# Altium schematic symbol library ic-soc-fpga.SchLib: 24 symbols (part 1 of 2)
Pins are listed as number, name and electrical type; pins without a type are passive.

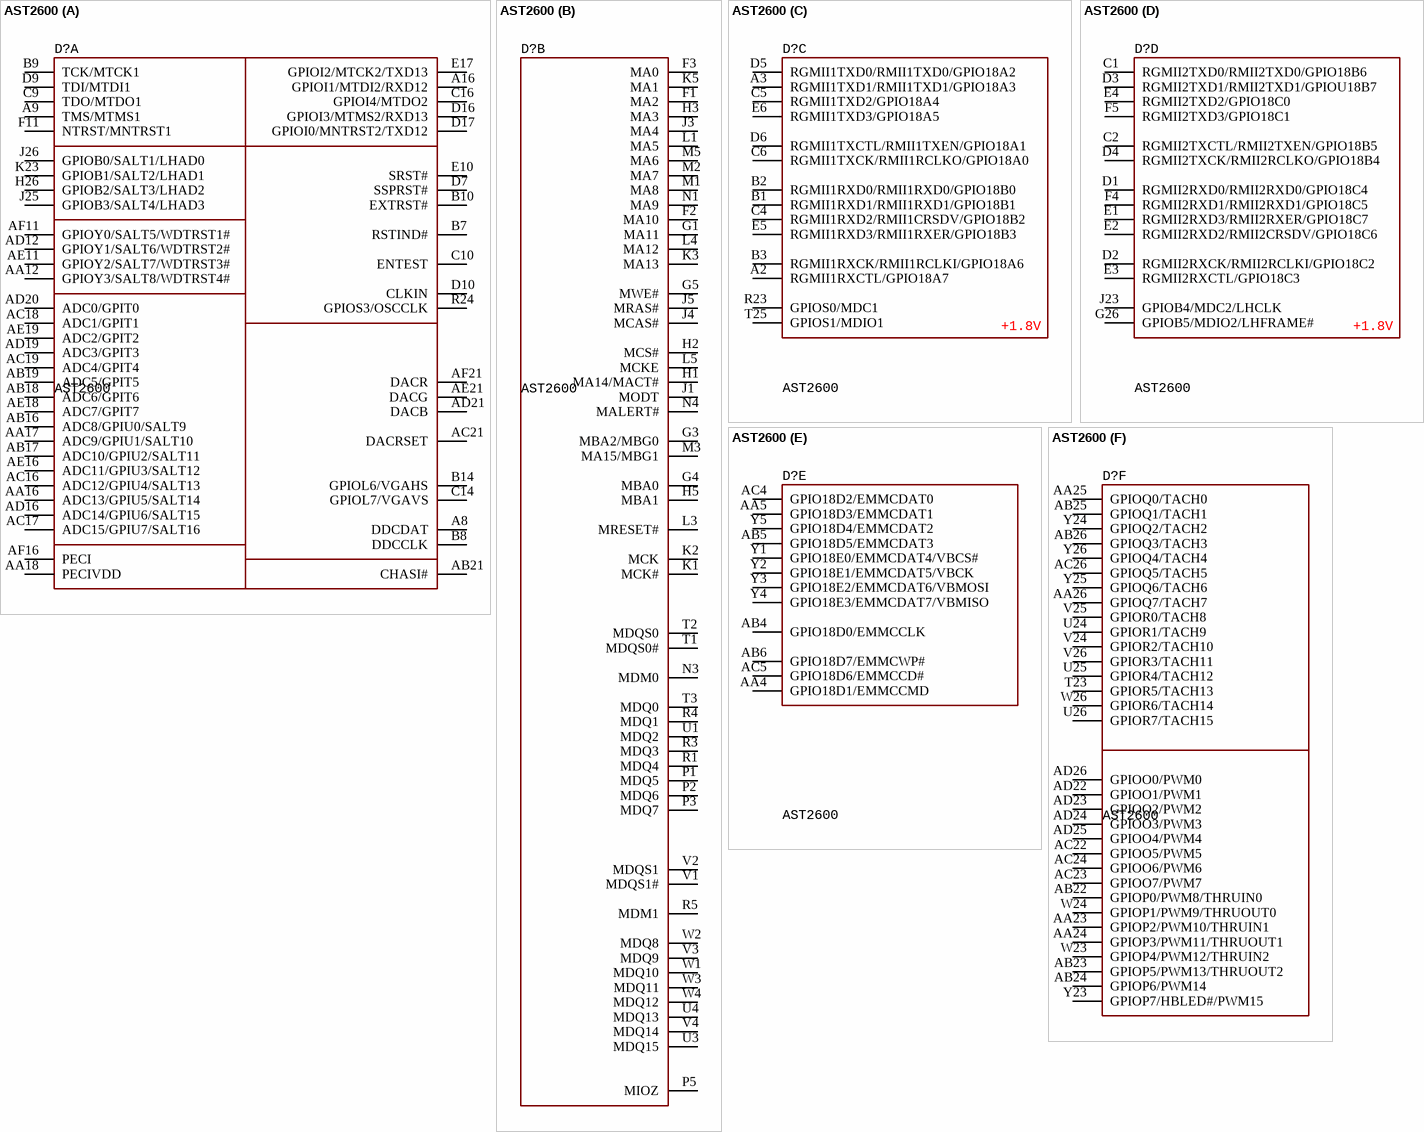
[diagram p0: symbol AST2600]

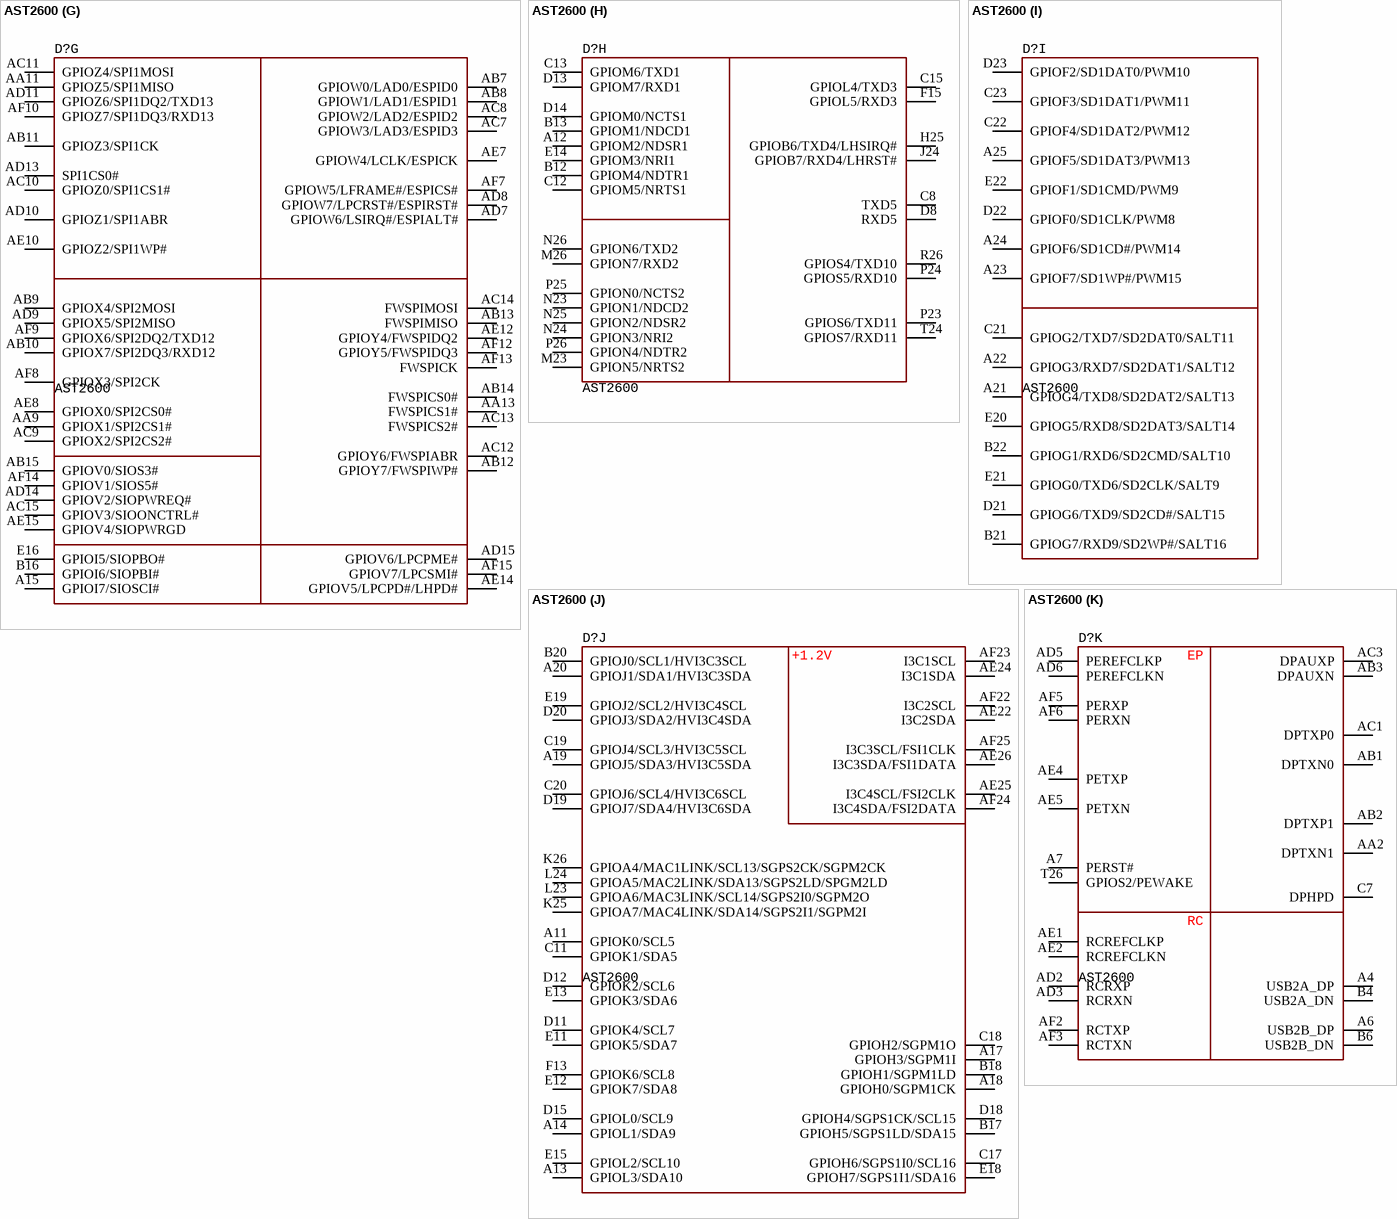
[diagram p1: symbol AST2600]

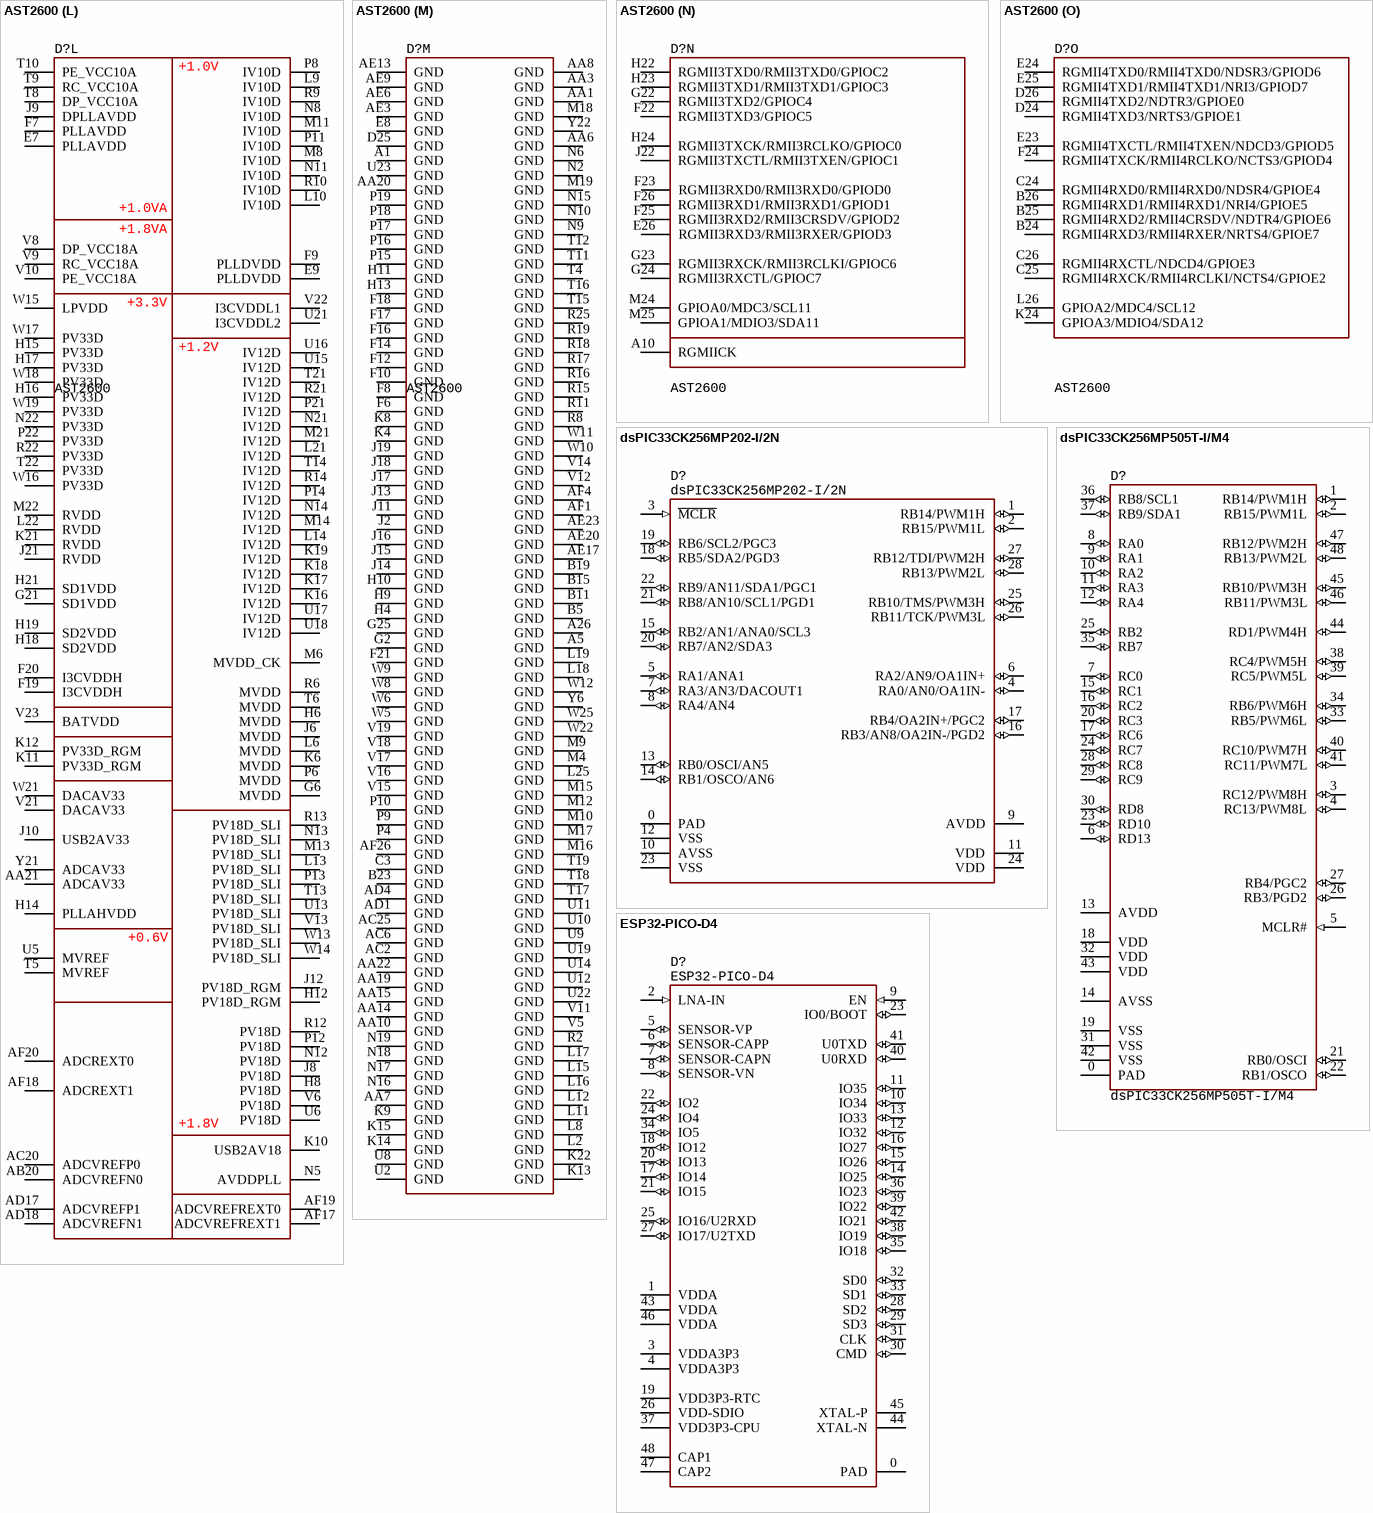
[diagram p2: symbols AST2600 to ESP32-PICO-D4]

## AST2600
designator D?
ARM SoC, Cortex-A7/M3, 1.2GHz, TFBGA-624, 0...+95°C; Manufacturer: ASPEED
footprint 624-TFBGA (21x21, pitch 0.8)
part A pins: A8 DDCDAT, A9 TMS/MTMS1, A16 GPIOI1/MTDI2/RXD12, AA12 GPIOY3/SALT8/WDTRST4#, AA16 ADC13/GPIU5/SALT14, AA17 ADC9/GPIU1/SALT10, AA18 PECIVDD, AB16 ADC8/GPIU0/SALT9, AB17 ADC10/GPIU2/SALT11, AB18 ADC6/GPIT6, AB19 ADC5/GPIT5, AB21 CHASI#, AC16 ADC12/GPIU4/SALT13, AC17 ADC15/GPIU7/SALT16, AC18 ADC1/GPIT1, AC19 ADC4/GPIT4, AC21 DACRSET, AD12 GPIOY1/SALT6/WDTRST2#, AD16 ADC14/GPIU6/SALT15, AD19 ADC3/GPIT3, AD20 ADC0/GPIT0, AD21 DACB, AE11 GPIOY2/SALT7/WDTRST3#, AE16 ADC11/GPIU3/SALT12, AE18 ADC7/GPIT7, AE19 ADC2/GPIT2, AE21 DACG, AF11 GPIOY0/SALT5/WDTRST1#, AF16 PECI, AF21 DACR, B7 RSTIND#, B8 DDCCLK, B9 TCK/MTCK1, B10 EXTRST#, B14 GPIOL6/VGAHS, C9 TDO/MTDO1, C10 ENTEST, C14 GPIOL7/VGAVS, C16 GPIOI4/MTDO2, D7 SSPRST#, D9 TDI/MTDI1, D10 CLKIN, D16 GPIOI3/MTMS2/RXD13, D17 GPIOI0/MNTRST2/TXD12, E10 SRST#, E17 GPIOI2/MTCK2/TXD13, F11 NTRST/MNTRST1, H26 GPIOB2/SALT3/LHAD2, J25 GPIOB3/SALT4/LHAD3, J26 GPIOB0/SALT1/LHAD0, K23 GPIOB1/SALT2/LHAD1, R24 GPIOS3/OSCCLK
part B pins: F1 MA2, F2 MA10, F3 MA0, G1 MA11, G3 MBA2/MBG0, G4 MBA0, G5 MWE#, H1 MA14/MACT#, H2 MCS#, H3 MA3, H5 MBA1, J1 MODT, J3 MA4, J4 MCAS#, J5 MRAS#, K1 MCK#, K2 MCK, K3 MA13, K5 MA1, L1 MA5, L3 MRESET#, L4 MA12, L5 MCKE, M1 MA8, M2 MA7, M3 MA15/MBG1, M5 MA6, N1 MA9, N3 MDM0, N4 MALERT#, P1 MDQ5, P2 MDQ6, P3 MDQ7, P5 MIOZ, R1 MDQ4, R3 MDQ3, R4 MDQ1, R5 MDM1, T1 MDQS0#, T2 MDQS0, T3 MDQ0, U1 MDQ2, U3 MDQ15, U4 MDQ13, V1 MDQS1#, V2 MDQS1, V3 MDQ9, V4 MDQ14, W1 MDQ10, W2 MDQ8, W3 MDQ11, W4 MDQ12
part C pins: A2 RGMII1RXCTL/GPIO18A7, A3 RGMII1TXD1/RMII1TXD1/GPIO18A3, B1 RGMII1RXD1/RMII1RXD1/GPIO18B1, B2 RGMII1RXD0/RMII1RXD0/GPIO18B0, B3 RGMII1RXCK/RMII1RCLKI/GPIO18A6, C4 RGMII1RXD2/RMII1CRSDV/GPIO18B2, C5 RGMII1TXD2/GPIO18A4, C6 RGMII1TXCK/RMII1RCLKO/GPIO18A0, D5 RGMII1TXD0/RMII1TXD0/GPIO18A2, D6 RGMII1TXCTL/RMII1TXEN/GPIO18A1, E5 RGMII1RXD3/RMII1RXER/GPIO18B3, E6 RGMII1TXD3/GPIO18A5, R23 GPIOS0/MDC1, T25 GPIOS1/MDIO1
part D pins: C1 RGMII2TXD0/RMII2TXD0/GPIO18B6, C2 RGMII2TXCTL/RMII2TXEN/GPIO18B5, D1 RGMII2RXD0/RMII2RXD0/GPIO18C4, D2 RGMII2RXCK/RMII2RCLKI/GPIO18C2, D3 RGMII2TXD1/RMII2TXD1/GPIOU18B7, D4 RGMII2TXCK/RMII2RCLKO/GPIO18B4, E1 RGMII2RXD3/RMII2RXER/GPIO18C7, E2 RGMII2RXD2/RMII2CRSDV/GPIO18C6, E3 RGMII2RXCTL/GPIO18C3, E4 RGMII2TXD2/GPIO18C0, F4 RGMII2RXD1/RMII2RXD1/GPIO18C5, F5 RGMII2TXD3/GPIO18C1, G26 GPIOB5/MDIO2/LHFRAME#, J23 GPIOB4/MDC2/LHCLK
part E pins: AA4 GPIO18D1/EMMCCMD, AA5 GPIO18D3/EMMCDAT1, AB4 GPIO18D0/EMMCCLK, AB5 GPIO18D5/EMMCDAT3, AB6 GPIO18D7/EMMCWP#, AC4 GPIO18D2/EMMCDAT0, AC5 GPIO18D6/EMMCCD#, Y1 GPIO18E0/EMMCDAT4/VBCS#, Y2 GPIO18E1/EMMCDAT5/VBCK, Y3 GPIO18E2/EMMCDAT6/VBMOSI, Y4 GPIO18E3/EMMCDAT7/VBMISO, Y5 GPIO18D4/EMMCDAT2
part F pins: AA23 GPIOP2/PWM10/THRUIN1, AA24 GPIOP3/PWM11/THRUOUT1, AA25 GPIOQ0/TACH0, AA26 GPIOQ7/TACH7, AB22 GPIOP0/PWM8/THRUIN0, AB23 GPIOP5/PWM13/THRUOUT2, AB24 GPIOP6/PWM14, AB25 GPIOQ1/TACH1, AB26 GPIOQ3/TACH3, AC22 GPIOO5/PWM5, AC23 GPIOO7/PWM7, AC24 GPIOO6/PWM6, AC26 GPIOQ5/TACH5, AD22 GPIOO1/PWM1, AD23 GPIOO2/PWM2, AD24 GPIOO3/PWM3, AD25 GPIOO4/PWM4, AD26 GPIOO0/PWM0, T23 GPIOR5/TACH13, U24 GPIOR1/TACH9, U25 GPIOR4/TACH12, U26 GPIOR7/TACH15, V24 GPIOR2/TACH10, V25 GPIOR0/TACH8, V26 GPIOR3/TACH11, W23 GPIOP4/PWM12/THRUIN2, W24 GPIOP1/PWM9/THRUOUT0, W26 GPIOR6/TACH14, Y23 GPIOP7/HBLED#/PWM15, Y24 GPIOQ2/TACH2, Y25 GPIOQ6/TACH6, Y26 GPIOQ4/TACH4
part G pins: A15 GPIOI7/SIOSCI#, AA9 GPIOX1/SPI2CS1#, AA11 GPIOZ5/SPI1MISO, AA13 FWSPICS1#, AB7 GPIOW0/LAD0/ESPID0, AB8 GPIOW1/LAD1/ESPID1, AB9 GPIOX4/SPI2MOSI, AB10 GPIOX7/SPI2DQ3/RXD12, AB11 GPIOZ3/SPI1CK, AB12 GPIOY7/FWSPIWP#, AB13 FWSPIMISO, AB14 FWSPICS0#, AB15 GPIOV0/SIOS3#, AC7 GPIOW3/LAD3/ESPID3, AC8 GPIOW2/LAD2/ESPID2, AC9 GPIOX2/SPI2CS2#, AC10 GPIOZ0/SPI1CS1#, AC11 GPIOZ4/SPI1MOSI, AC12 GPIOY6/FWSPIABR, AC13 FWSPICS2#, AC14 FWSPIMOSI, AC15 GPIOV3/SIOONCTRL#, AD7 GPIOW6/LSIRQ#/ESPIALT#, AD8 GPIOW7/LPCRST#/ESPIRST#, AD9 GPIOX5/SPI2MISO, AD10 GPIOZ1/SPI1ABR, AD11 GPIOZ6/SPI1DQ2/TXD13, AD13 SPI1CS0#, AD14 GPIOV2/SIOPWREQ#, AD15 GPIOV6/LPCPME#, AE7 GPIOW4/LCLK/ESPICK, AE8 GPIOX0/SPI2CS0#, AE10 GPIOZ2/SPI1WP#, AE12 GPIOY4/FWSPIDQ2, AE14 GPIOV5/LPCPD#/LHPD#, AE15 GPIOV4/SIOPWRGD, AF7 GPIOW5/LFRAME#/ESPICS#, AF8 GPIOX3/SPI2CK, AF9 GPIOX6/SPI2DQ2/TXD12, AF10 GPIOZ7/SPI1DQ3/RXD13, AF12 GPIOY5/FWSPIDQ3, AF13 FWSPICK, AF14 GPIOV1/SIOS5#, AF15 GPIOV7/LPCSMI#, B16 GPIOI6/SIOPBI#, E16 GPIOI5/SIOPBO#
part H pins: A12 GPIOM2/NDSR1, B12 GPIOM4/NDTR1, B13 GPIOM1/NDCD1, C8 TXD5, C12 GPIOM5/NRTS1, C13 GPIOM6/TXD1, C15 GPIOL4/TXD3, D8 RXD5, D13 GPIOM7/RXD1, D14 GPIOM0/NCTS1, E14 GPIOM3/NRI1, F15 GPIOL5/RXD3, H25 GPIOB6/TXD4/LHSIRQ#, J24 GPIOB7/RXD4/LHRST#, M23 GPION5/NRTS2, M26 GPION7/RXD2, N23 GPION1/NDCD2, N24 GPION3/NRI2, N25 GPION2/NDSR2, N26 GPION6/TXD2, P23 GPIOS6/TXD11, P24 GPIOS5/RXD10, P25 GPION0/NCTS2, P26 GPION4/NDTR2, R26 GPIOS4/TXD10, T24 GPIOS7/RXD11
part I pins: A21 GPIOG4/TXD8/SD2DAT2/SALT13, A22 GPIOG3/RXD7/SD2DAT1/SALT12, A23 GPIOF7/SD1WP#/PWM15, A24 GPIOF6/SD1CD#/PWM14, A25 GPIOF5/SD1DAT3/PWM13, B21 GPIOG7/RXD9/SD2WP#/SALT16, B22 GPIOG1/RXD6/SD2CMD/SALT10, C21 GPIOG2/TXD7/SD2DAT0/SALT11, C22 GPIOF4/SD1DAT2/PWM12, C23 GPIOF3/SD1DAT1/PWM11, D21 GPIOG6/TXD9/SD2CD#/SALT15, D22 GPIOF0/SD1CLK/PWM8, D23 GPIOF2/SD1DAT0/PWM10, E20 GPIOG5/RXD8/SD2DAT3/SALT14, E21 GPIOG0/TXD6/SD2CLK/SALT9, E22 GPIOF1/SD1CMD/PWM9
part J pins: A11 GPIOK0/SCL5, A13 GPIOL3/SDA10, A14 GPIOL1/SDA9, A17 GPIOH3/SGPM1I, A18 GPIOH0/SGPM1CK, A19 GPIOJ5/SDA3/HVI3C5SDA, A20 GPIOJ1/SDA1/HVI3C3SDA, AE22 I3C2SDA, AE24 I3C1SDA, AE25 I3C4SCL/FSI2CLK, AE26 I3C3SDA/FSI1DATA, AF22 I3C2SCL, AF23 I3C1SCL, AF24 I3C4SDA/FSI2DATA, AF25 I3C3SCL/FSI1CLK, B17 GPIOH5/SGPS1LD/SDA15, B18 GPIOH1/SGPM1LD, B20 GPIOJ0/SCL1/HVI3C3SCL, C11 GPIOK1/SDA5, C17 GPIOH6/SGPS1I0/SCL16, C18 GPIOH2/SGPM1O, C19 GPIOJ4/SCL3/HVI3C5SCL, C20 GPIOJ6/SCL4/HVI3C6SCL, D11 GPIOK4/SCL7, D12 GPIOK2/SCL6, D15 GPIOL0/SCL9, D18 GPIOH4/SGPS1CK/SCL15, D19 GPIOJ7/SDA4/HVI3C6SDA, D20 GPIOJ3/SDA2/HVI3C4SDA, E11 GPIOK5/SDA7, E12 GPIOK7/SDA8, E13 GPIOK3/SDA6, E15 GPIOL2/SCL10, E18 GPIOH7/SGPS1I1/SDA16, E19 GPIOJ2/SCL2/HVI3C4SCL, F13 GPIOK6/SCL8, K25 GPIOA7/MAC4LINK/SDA14/SGPS2I1/SGPM2I, K26 GPIOA4/MAC1LINK/SCL13/SGPS2CK/SGPM2CK, L23 GPIOA6/MAC3LINK/SCL14/SGPS2I0/SGPM2O, L24 GPIOA5/MAC2LINK/SDA13/SGPS2LD/SPGM2LD
part K pins: A4 USB2A_DP, A6 USB2B_DP, A7 PERST#, AA2 DPTXN1, AB1 DPTXN0, AB2 DPTXP1, AB3 DPAUXN, AC1 DPTXP0, AC3 DPAUXP, AD2 RCRXP, AD3 RCRXN, AD5 PEREFCLKP, AD6 PEREFCLKN, AE1 RCREFCLKP, AE2 RCREFCLKN, AE4 PETXP, AE5 PETXN, AF2 RCTXP, AF3 RCTXN, AF5 PERXP, AF6 PERXN, B4 USB2A_DN, B6 USB2B_DN, C7 DPHPD, T26 GPIOS2/PEWAKE
part L pins: AA21 ADCAV33, AB20 ADCVREFN0, AC20 ADCVREFP0, AD17 ADCVREFP1, AD18 ADCVREFN1, AF17 ADCVREFREXT1, AF18 ADCREXT1, AF19 ADCVREFREXT0, AF20 ADCREXT0, E7 PLLAVDD, E9 PLLDVDD, F7 PLLAVDD, F9 PLLDVDD, F19 I3CVDDH, F20 I3CVDDH, G6 MVDD, G21 SD1VDD, H6 MVDD, H8 PV18D, H12 PV18D_RGM, H14 PLLAHVDD, H15 PV33D, H16 PV33D, H17 PV33D, H18 SD2VDD, H19 SD2VDD, H21 SD1VDD, J6 MVDD, J8 PV18D, J9 DPLLAVDD, J10 USB2AV33, J12 PV18D_RGM, J21 RVDD, K6 MVDD, K10 USB2AV18, K11 PV33D_RGM, K12 PV33D_RGM, K16 IV12D, K17 IV12D, K18 IV12D, K19 IV12D, K21 RVDD, L6 MVDD, L9 IV10D, L10 IV10D, L13 PV18D_SLI, L14 IV12D, L21 IV12D, L22 RVDD, M6 MVDD_CK, M8 IV10D, M11 IV10D, M13 PV18D_SLI, M14 IV12D, M21 IV12D, M22 RVDD, N5 AVDDPLL, N8 IV10D, N11 IV10D, N12 PV18D, N13 PV18D_SLI, N14 IV12D, N21 IV12D, N22 PV33D, P6 MVDD, P8 IV10D, P11 IV10D, P12 PV18D, P13 PV18D_SLI, P14 IV12D, P21 IV12D, P22 PV33D, R6 MVDD, R9 IV10D, R10 IV10D, R12 PV18D, R13 PV18D_SLI, R14 IV12D, R21 IV12D, R22 PV33D, T5 MVREF, T6 MVDD, T8 DP_VCC10A, T9 RC_VCC10A, T10 PE_VCC10A, T13 PV18D_SLI, T14 IV12D, T21 IV12D, T22 PV33D, U5 MVREF, U6 PV18D, U13 PV18D_SLI, U15 IV12D, U16 IV12D, U17 IV12D, U18 IV12D, U21 I3CVDDL2, V6 PV18D, V8 DP_VCC18A, V9 RC_VCC18A, V10 PE_VCC18A, V13 PV18D_SLI, V21 DACAV33, V22 I3CVDDL1, V23 BATVDD, W13 PV18D_SLI, W14 PV18D_SLI, W15 LPVDD, W16 PV33D, W17 PV33D, W18 PV33D, W19 PV33D, W21 DACAV33, Y21 ADCAV33
part M pins: A1 GND, A5 GND, A26 GND, AA1 GND, AA3 GND, AA6 GND, AA7 GND, AA8 GND, AA10 GND, AA14 GND, AA15 GND, AA19 GND, AA20 GND, AA22 GND, AC2 GND, AC6 GND, AC25 GND, AD1 GND, AD4 GND, AE3 GND, AE6 GND, AE9 GND, AE13 GND, AE17 GND, AE20 GND, AE23 GND, AF1 GND, AF4 GND, AF26 GND, B5 GND, B11 GND, B15 GND, B19 GND, B23 GND, C3 GND, D25 GND, E8 GND, F6 GND, F8 GND, F10 GND, F12 GND, F14 GND, F16 GND, F17 GND, F18 GND, F21 GND, G2 GND, G25 GND, H4 GND, H9 GND, H10 GND, H11 GND, H13 GND, J2 GND, J11 GND, J13 GND, J14 GND, J15 GND, J16 GND, J17 GND, J18 GND, J19 GND, K4 GND, K8 GND, K9 GND, K13 GND, K14 GND, K15 GND, K22 GND, L2 GND, L8 GND, L11 GND, L12 GND, L15 GND, L16 GND, L17 GND, L18 GND, L19 GND, L25 GND, M4 GND, M9 GND, M10 GND, M12 GND, M15 GND, M16 GND, M17 GND, M18 GND, M19 GND, N2 GND, N6 GND, N9 GND, N10 GND, N15 GND, N16 GND, N17 GND, N18 GND, N19 GND, P4 GND, P9 GND, P10 GND, P15 GND, P16 GND, P17 GND, P18 GND, P19 GND, R2 GND, R8 GND, R11 GND, R15 GND, R16 GND, R17 GND, R18 GND, R19 GND, R25 GND, T4 GND, T11 GND, T12 GND, T15 GND, T16 GND, T17 GND, T18 GND, T19 GND, U2 GND, U8 GND, U9 GND, U10 GND, U11 GND, U12 GND, U14 GND, U19 GND, U22 GND, U23 GND, V5 GND, V11 GND, V12 GND, V14 GND, V15 GND, V16 GND, V17 GND, V18 GND, V19 GND, W5 GND, W6 GND, W8 GND, W9 GND, W10 GND, W11 GND, W12 GND, W22 GND, W25 GND, Y6 GND, Y22 GND
part N pins: A10 RGMIICK, E26 RGMII3RXD3/RMII3RXER/GPIOD3, F22 RGMII3TXD3/GPIOC5, F23 RGMII3RXD0/RMII3RXD0/GPIOD0, F25 RGMII3RXD2/RMII3CRSDV/GPIOD2, F26 RGMII3RXD1/RMII3RXD1/GPIOD1, G22 RGMII3TXD2/GPIOC4, G23 RGMII3RXCK/RMII3RCLKI/GPIOC6, G24 RGMII3RXCTL/GPIOC7, H22 RGMII3TXD0/RMII3TXD0/GPIOC2, H23 RGMII3TXD1/RMII3TXD1/GPIOC3, H24 RGMII3TXCK/RMII3RCLKO/GPIOC0, J22 RGMII3TXCTL/RMII3TXEN/GPIOC1, M24 GPIOA0/MDC3/SCL11, M25 GPIOA1/MDIO3/SDA11
part O pins: B24 RGMII4RXD3/RMII4RXER/NRTS4/GPIOE7, B25 RGMII4RXD2/RMII4CRSDV/NDTR4/GPIOE6, B26 RGMII4RXD1/RMII4RXD1/NRI4/GPIOE5, C24 RGMII4RXD0/RMII4RXD0/NDSR4/GPIOE4, C25 RGMII4RXCK/RMII4RCLKI/NCTS4/GPIOE2, C26 RGMII4RXCTL/NDCD4/GPIOE3, D24 RGMII4TXD3/NRTS3/GPIOE1, D26 RGMII4TXD2/NDTR3/GPIOE0, E23 RGMII4TXCTL/RMII4TXEN/NDCD3/GPIOD5, E24 RGMII4TXD0/RMII4TXD0/NDSR3/GPIOD6, E25 RGMII4TXD1/RMII4TXD1/NRI3/GPIOD7, F24 RGMII4TXCK/RMII4RCLKO/NCTS3/GPIOD4, K24 GPIOA3/MDIO4/SDA12, L26 GPIOA2/MDC4/SCL12

## dsPIC33CK256MP202-I/2N
designator D?
DSP, 100MHz, 256KB ROM, 24KB RAM, 3...3.6V, QFN-28, -40...+85°C; Manufacturer: Microchip
footprint 28-QFN (6x6, pitch 0.65) (6x6 mm, pitch 0.65 mm, power pad)
pins: 0 PAD, 1 RB14/PWM1H (io), 2 RB15/PWM1L (io), 3 ~{MCLR} (in), 4 RA0/AN0/OA1IN- (io), 5 RA1/ANA1 (io), 6 RA2/AN9/OA1IN+ (io), 7 RA3/AN3/DACOUT1 (io), 8 RA4/AN4 (io), 9 AVDD, 10 AVSS, 11 VDD, 12 VSS, 13 RB0/OSCI/AN5 (io), 14 RB1/OSCO/AN6 (io), 15 RB2/AN1/ANA0/SCL3 (io), 16 RB3/AN8/OA2IN-/PGD2 (io), 17 RB4/OA2IN+/PGC2 (io), 18 RB5/SDA2/PGD3 (io), 19 RB6/SCL2/PGC3 (io), 20 RB7/AN2/SDA3 (io), 21 RB8/AN10/SCL1/PGD1 (io), 22 RB9/AN11/SDA1/PGC1 (io), 23 VSS, 24 VDD, 25 RB10/TMS/PWM3H (io), 26 RB11/TCK/PWM3L (io), 27 RB12/TDI/PWM2H (io), 28 RB13/PWM2L (io)

## dsPIC33CK256MP505T-I/M4
designator D?
DSP, 100MHz, 256KB ROM, 24KB RAM, 3...3.6V, UFQFN-48, -40...+150°C; Manufacturer: Microchip
footprint 48-QFN (6x6, pitch 0.4) (6x6 mm, pitch 0.4 mm, power pad)
pins: 0 PAD, 1 RB14/PWM1H (io), 2 RB15/PWM1L (io), 3 RC12/PWM8H (io), 4 RC13/PWM8L (io), 5 MCLR# (in), 6 RD13 (io), 7 RC0 (io), 8 RA0 (io), 9 RA1 (io), 10 RA2 (io), 11 RA3 (io), 12 RA4 (io), 13 AVDD, 14 AVSS, 15 RC1 (io), 16 RC2 (io), 17 RC6 (io), 18 VDD, 19 VSS, 20 RC3 (io), 21 RB0/OSCI (io), 22 RB1/OSCO (io), 23 RD10 (io), 24 RC7 (io), 25 RB2 (io), 26 RB3/PGD2 (io), 27 RB4/PGC2 (io), 28 RC8 (io), 29 RC9 (io), 30 RD8 (io), 31 VSS, 32 VDD, 33 RB5/PWM6L (io), 34 RB6/PWM6H (io), 35 RB7 (io), 36 RB8/SCL1 (io), 37 RB9/SDA1 (io), 38 RC4/PWM5H (io), 39 RC5/PWM5L (io), 40 RC10/PWM7H (io), 41 RC11/PWM7L (io), 42 VSS, 43 VDD, 44 RD1/PWM4H (io), 45 RB10/PWM3H (io), 46 RB11/PWM3L (io), 47 RB12/PWM2H (io), 48 RB13/PWM2L (io)

## ESP32-PICO-D4
designator D?
RF SiP, WiFi/BT, 150 Mbps, 20 dBm, 4 Mb ROM, 512 kB RAM, QFN-48, -40...+85°C; Manufacturer: Espressif Systems
footprint 48-LGA (7x7, pitch 0.5) (7x7 mm, pitch 0.5 mm, power pad)
pins: 0 PAD, 1 VDDA, 2 LNA-IN (in), 3 VDDA3P3, 4 VDDA3P3, 5 SENSOR-VP (io), 6 SENSOR-CAPP (io), 7 SENSOR-CAPN (io), 8 SENSOR-VN (io), 9 EN (in), 10 IO34 (io), 11 IO35 (io), 12 IO32 (io), 13 IO33 (io), 14 IO25 (io), 15 IO26 (io), 16 IO27 (io), 17 IO14 (io), 18 IO12 (io), 19 VDD3P3-RTC, 20 IO13 (io), 21 IO15 (io), 22 IO2 (io), 23 IO0/BOOT (io), 24 IO4 (io), 25 IO16/U2RXD (io), 26 VDD-SDIO, 27 IO17/U2TXD (io), 28 SD2 (io), 29 SD3 (io), 30 CMD (io), 31 CLK (io), 32 SD0 (io), 33 SD1 (io), 34 IO5 (io), 35 IO18 (io), 36 IO23 (io), 37 VDD3P3-CPU, 38 IO19 (io), 39 IO22 (io), 40 U0RXD (io), 41 U0TXD (io), 42 IO21 (io), 43 VDDA, 44 XTAL-N, 45 XTAL-P, 46 VDDA, 47 CAP2, 48 CAP1

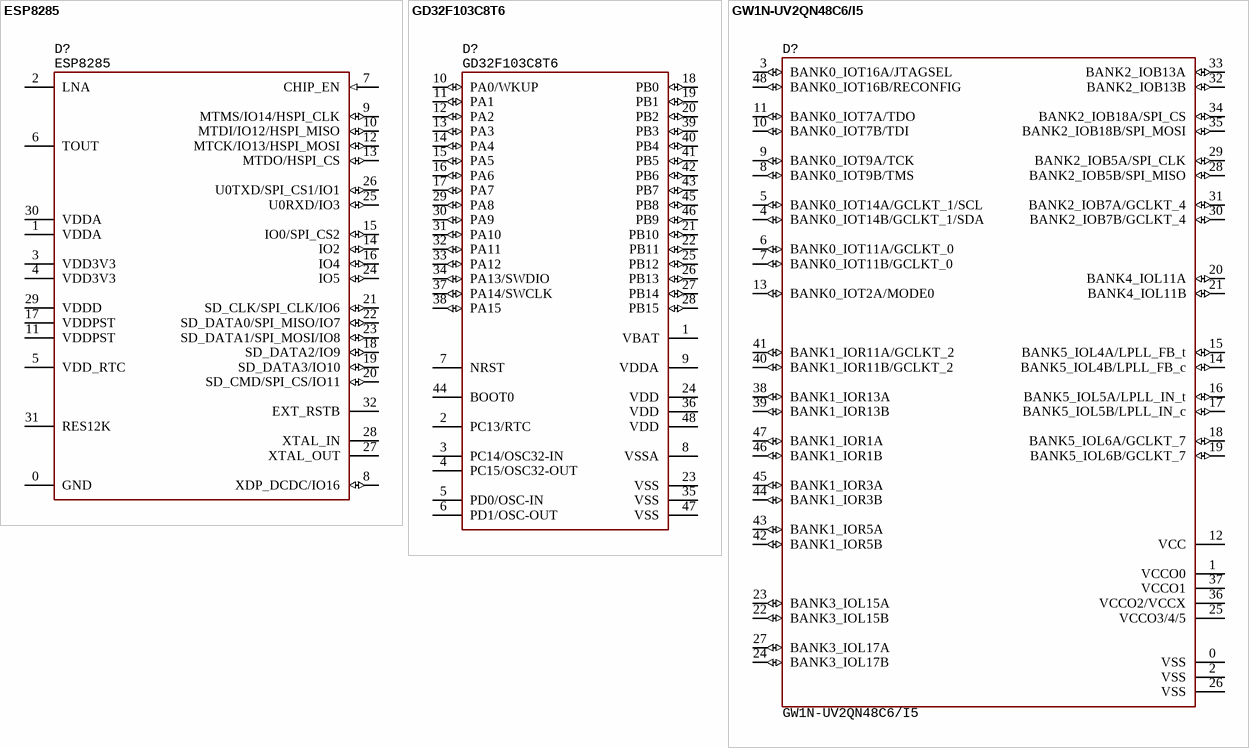
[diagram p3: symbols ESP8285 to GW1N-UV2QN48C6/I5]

## ESP8285
designator D?
RF SoC, WiFi/BT, 72 Mbps, 19 dBm, 1024 kB ROM, 50 kB RAM, QFN-32, -40...+85°C; Manufacturer: Espressif Systems
footprint 32-QFN (5x5, pitch 0.5) (5x5 mm, pitch 0.5 mm, power pad)
pins: 0 GND, 1 VDDA, 2 LNA, 3 VDD3V3, 4 VDD3V3, 5 VDD_RTC, 6 TOUT, 7 CHIP_EN (in), 8 XDP_DCDC/IO16 (io), 9 MTMS/IO14/HSPI_CLK (io), 10 MTDI/IO12/HSPI_MISO (io), 11 VDDPST, 12 MTCK/IO13/HSPI_MOSI (io), 13 MTDO/HSPI_CS (io), 14 IO2 (io), 15 IO0/SPI_CS2 (io), 16 IO4 (io), 17 VDDPST, 18 SD_DATA2/IO9 (io), 19 SD_DATA3/IO10 (io), 20 SD_CMD/SPI_CS/IO11 (io), 21 SD_CLK/SPI_CLK/IO6 (io), 22 SD_DATA0/SPI_MISO/IO7 (io), 23 SD_DATA1/SPI_MOSI/IO8 (io), 24 IO5 (io), 25 U0RXD/IO3 (io), 26 U0TXD/SPI_CS1/IO1 (io), 27 XTAL_OUT, 28 XTAL_IN, 29 VDDD, 30 VDDA, 31 RES12K, 32 EXT_RSTB

## GD32F103C8T6
designator D?
Cortex-M3, 108MHz, 64KB ROM, 20KB RAM, 2...3.6V, LQFP-48, -40...+85°C; Manufacturer: GigaDevices
footprint 48-LQFP (QFP, 48-Leads, Body 7x7mm, Pitch 0.5mm, IPC Medium Density)
pins: 1 VBAT, 2 PC13/RTC, 3 PC14/OSC32-IN, 4 PC15/OSC32-OUT, 5 PD0/OSC-IN, 6 PD1/OSC-OUT, 7 NRST, 8 VSSA, 9 VDDA, 10 PA0/WKUP (io), 11 PA1 (io), 12 PA2 (io), 13 PA3 (io), 14 PA4 (io), 15 PA5 (io), 16 PA6 (io), 17 PA7 (io), 18 PB0 (io), 19 PB1 (io), 20 PB2 (io), 21 PB10 (io), 22 PB11 (io), 23 VSS, 24 VDD, 25 PB12 (io), 26 PB13 (io), 27 PB14 (io), 28 PB15 (io), 29 PA8 (io), 30 PA9 (io), 31 PA10 (io), 32 PA11 (io), 33 PA12 (io), 34 PA13/SWDIO (io), 35 VSS, 36 VDD, 37 PA14/SWCLK (io), 38 PA15 (io), 39 PB3 (io), 40 PB4 (io), 41 PB5 (io), 42 PB6 (io), 43 PB7 (io), 44 BOOT0, 45 PB8 (io), 46 PB9 (io), 47 VSS, 48 VDD

## GW1N-UV2QN48C6/I5
designator D?
FPGA, 2304 LUT, 72 kbit RAM, 96 Kb ROM, 40I/O, supply 1.71...3.6V, QFN-48, -40...+100°C; Manufacturer: Gowin
footprint 48-QFN (6x6, pitch 0.4) (6x6 mm, pitch 0.4 mm, power pad)
pins: 0 VSS, 1 VCCO0, 2 VSS, 3 BANK0_IOT16A/JTAGSEL (io), 4 BANK0_IOT14B/GCLKT_1/SDA (io), 5 BANK0_IOT14A/GCLKT_1/SCL (io), 6 BANK0_IOT11A/GCLKT_0 (io), 7 BANK0_IOT11B/GCLKT_0 (io), 8 BANK0_IOT9B/TMS (io), 9 BANK0_IOT9A/TCK (io), 10 BANK0_IOT7B/TDI (io), 11 BANK0_IOT7A/TDO (io), 12 VCC, 13 BANK0_IOT2A/MODE0 (io), 14 BANK5_IOL4B/LPLL_FB_c (io), 15 BANK5_IOL4A/LPLL_FB_t (io), 16 BANK5_IOL5A/LPLL_IN_t (io), 17 BANK5_IOL5B/LPLL_IN_c (io), 18 BANK5_IOL6A/GCLKT_7 (io), 19 BANK5_IOL6B/GCLKT_7 (io), 20 BANK4_IOL11A (io), 21 BANK4_IOL11B (io), 22 BANK3_IOL15B (io), 23 BANK3_IOL15A (io), 24 BANK3_IOL17B (io), 25 VCCO3/4/5, 26 VSS, 27 BANK3_IOL17A (io), 28 BANK2_IOB5B/SPI_MISO (io), 29 BANK2_IOB5A/SPI_CLK (io), 30 BANK2_IOB7B/GCLKT_4 (io), 31 BANK2_IOB7A/GCLKT_4 (io), 32 BANK2_IOB13B (io), 33 BANK2_IOB13A (io), 34 BANK2_IOB18A/SPI_CS (io), 35 BANK2_IOB18B/SPI_MOSI (io), 36 VCCO2/VCCX, 37 VCCO1, 38 BANK1_IOR13A (io), 39 BANK1_IOR13B (io), 40 BANK1_IOR11B/GCLKT_2 (io), 41 BANK1_IOR11A/GCLKT_2 (io), 42 BANK1_IOR5B (io), 43 BANK1_IOR5A (io), 44 BANK1_IOR3B (io), 45 BANK1_IOR3A (io), 46 BANK1_IOR1B (io), 47 BANK1_IOR1A (io), 48 BANK0_IOT16B/RECONFIG (io)

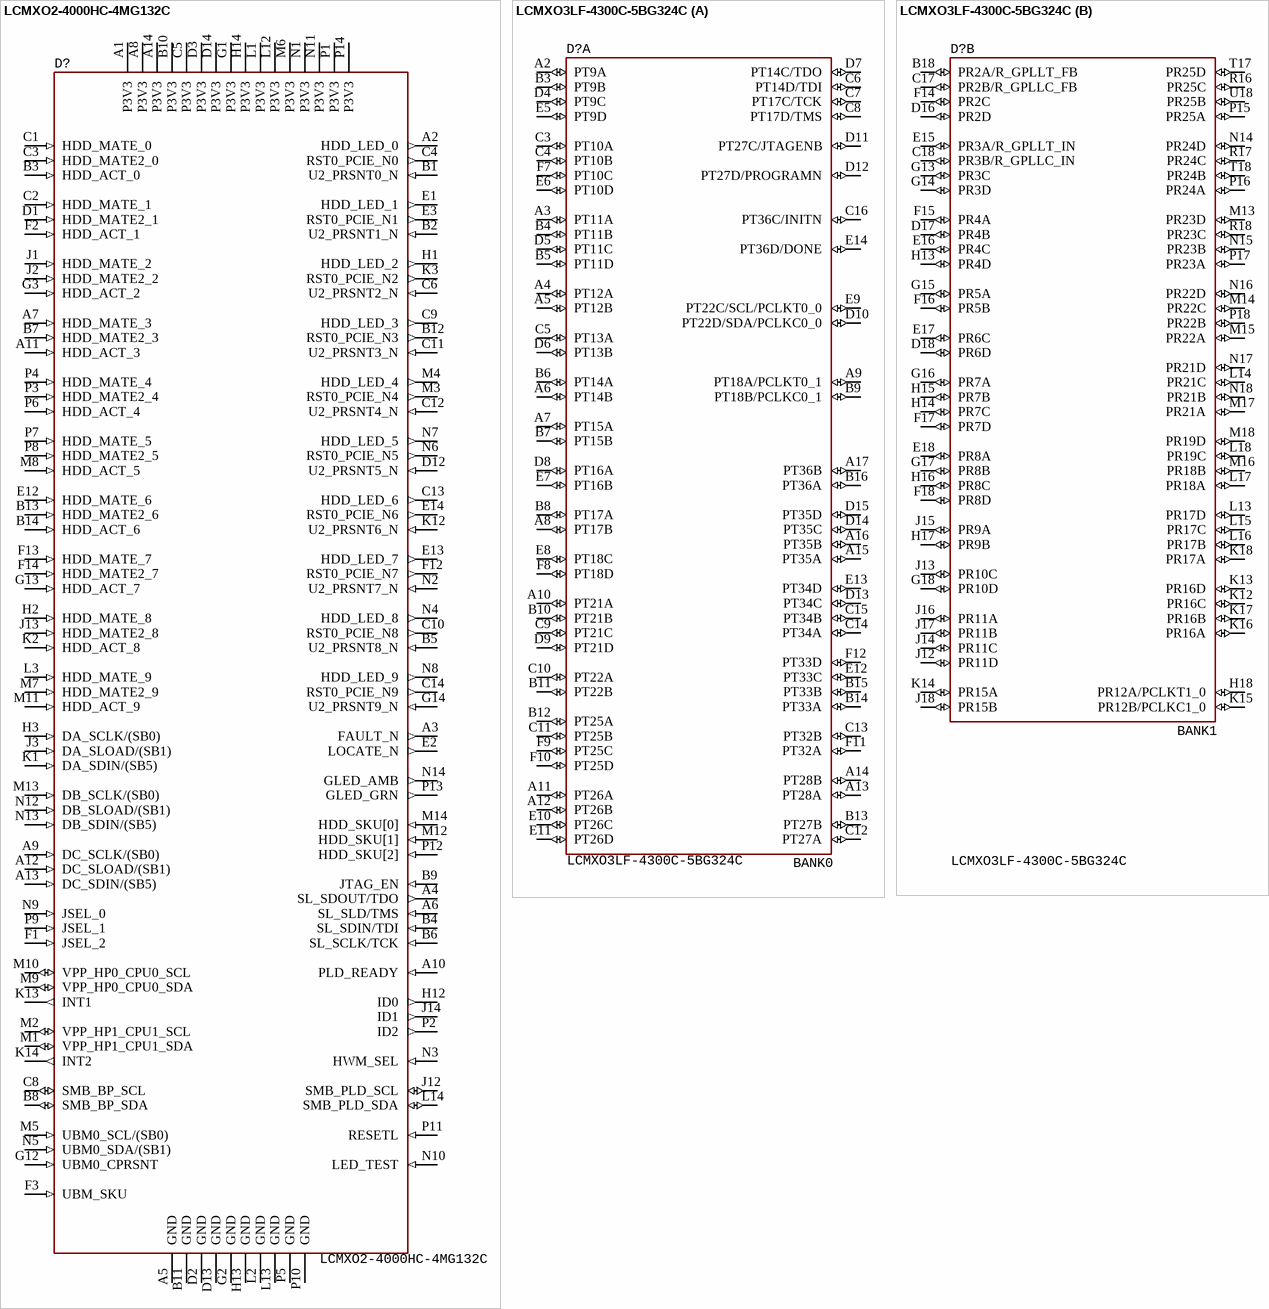
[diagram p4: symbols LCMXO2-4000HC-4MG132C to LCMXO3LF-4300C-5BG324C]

## LCMXO2-4000HC-4MG132C
designator D?
FPGA, MachXO2, 4320LE, 269MHz, 104I/O, supply core 2.5/3.3V, CSBGA-132, 0...+85°C; Manufacturer: Lattice; Manufacturer: Lattice Semiconductor
footprint 132-CSBGA (8x8, pitch 0.5) (CSBGA, 132-Leads, Body 8,00x8,00mmx1,35mm, Pitch 0,50mm)
pins: A1 P3V3 (power), A2 HDD_LED_0 (out), A3 FAULT_N (out), A4 SL_SDOUT/TDO (out), A5 GND (power), A6 SL_SLD/TMS (in), A7 HDD_MATE_3 (in), A8 P3V3 (power), A9 DC_SCLK/(SB0) (in), A10 PLD_READY (in), A11 HDD_ACT_3 (in), A12 DC_SLOAD/(SB1) (in), A13 DC_SDIN/(SB5) (in), A14 P3V3 (power), B1 U2_PRSNT0_N (in), B2 U2_PRSNT1_N (in), B3 HDD_ACT_0 (in), B4 SL_SDIN/TDI (in), B5 U2_PRSNT8_N (in), B6 SL_SCLK/TCK (in), B7 HDD_MATE2_3 (in), B8 SMB_BP_SDA (io), B9 JTAG_EN (in), B10 P3V3 (power), B11 GND (power), B12 RST0_PCIE_N3 (out), B13 HDD_MATE2_6 (in), B14 HDD_ACT_6 (in), C1 HDD_MATE_0 (in), C2 HDD_MATE_1 (in), C3 HDD_MATE2_0 (in), C4 RST0_PCIE_N0 (out), C5 P3V3 (power), C6 U2_PRSNT2_N (in), C8 SMB_BP_SCL (io), C9 HDD_LED_3 (out), C10 RST0_PCIE_N8 (out), C11 U2_PRSNT3_N (in), C12 U2_PRSNT4_N (in), C13 HDD_LED_6 (out), C14 RST0_PCIE_N9 (out), D1 HDD_MATE2_1 (in), D2 GND (power), D3 P3V3 (power), D12 U2_PRSNT5_N (in), D13 GND (power), D14 P3V3 (power), E1 HDD_LED_1 (out), E2 LOCATE_N (out), E3 RST0_PCIE_N1 (out), E12 HDD_MATE_6 (in), E13 HDD_LED_7 (out), E14 RST0_PCIE_N6 (out), F1 JSEL_2 (in), F2 HDD_ACT_1 (in), F3 UBM_SKU (in), F12 RST0_PCIE_N7 (out), F13 HDD_MATE_7 (in), F14 HDD_MATE2_7 (in), G1 P3V3 (power), G2 GND (power), G3 HDD_ACT_2 (in), G12 UBM0_CPRSNT (in), G13 HDD_ACT_7 (in), G14 U2_PRSNT9_N (in), H1 HDD_LED_2 (out), H2 HDD_MATE_8 (in), H3 DA_SCLK/(SB0) (in), H12 ID0 (out), H13 GND (power), H14 P3V3 (power), J1 HDD_MATE_2 (in), J2 HDD_MATE2_2 (in), J3 DA_SLOAD/(SB1) (in), J12 SMB_PLD_SCL (io), J13 HDD_MATE2_8 (in), J14 ID1 (out), K1 DA_SDIN/(SB5) (in), K2 HDD_ACT_8 (in), K3 RST0_PCIE_N2 (out), K12 U2_PRSNT6_N (in), K13 INT1 (out), K14 INT2 (out), L1 P3V3 (power), L2 GND (power), L3 HDD_MATE_9 (in), L12 P3V3 (power), L13 GND (power), L14 SMB_PLD_SDA (io), M1 VPP_HP1_CPU1_SDA (io), M2 VPP_HP1_CPU1_SCL (io), M3 RST0_PCIE_N4 (out), M4 HDD_LED_4 (out), M5 UBM0_SCL/(SB0) (in), M6 P3V3 (power), M7 HDD_MATE2_9 (in), M8 HDD_ACT_5 (in), M9 VPP_HP0_CPU0_SDA (io), M10 VPP_HP0_CPU0_SCL (io), M11 HDD_ACT_9 (in), M12 HDD_SKU[1] (in), M13 DB_SCLK/(SB0) (in), M14 HDD_SKU[0] (in), N1 P3V3 (power), N2 U2_PRSNT7_N (in), N3 HWM_SEL (in), N4 HDD_LED_8 (out), N5 UBM0_SDA/(SB1) (in), N6 RST0_PCIE_N5 (out), N7 HDD_LED_5 (out), N8 HDD_LED_9 (out), N9 JSEL_0 (in), N10 LED_TEST (in), N11 P3V3 (power), N12 DB_SLOAD/(SB1) (in), N13 DB_SDIN/(SB5) (in), N14 GLED_AMB (out), P1 P3V3 (power), P2 ID2 (out), P3 HDD_MATE2_4 (in), P4 HDD_MATE_4 (in), P5 GND (power), P6 HDD_ACT_4 (in), P7 HDD_MATE_5 (in), P8 HDD_MATE2_5 (in), P9 JSEL_1 (in), P10 GND (power), P11 RESETL (in), P12 HDD_SKU[2] (in), P13 GLED_GRN (out), P14 P3V3 (power)

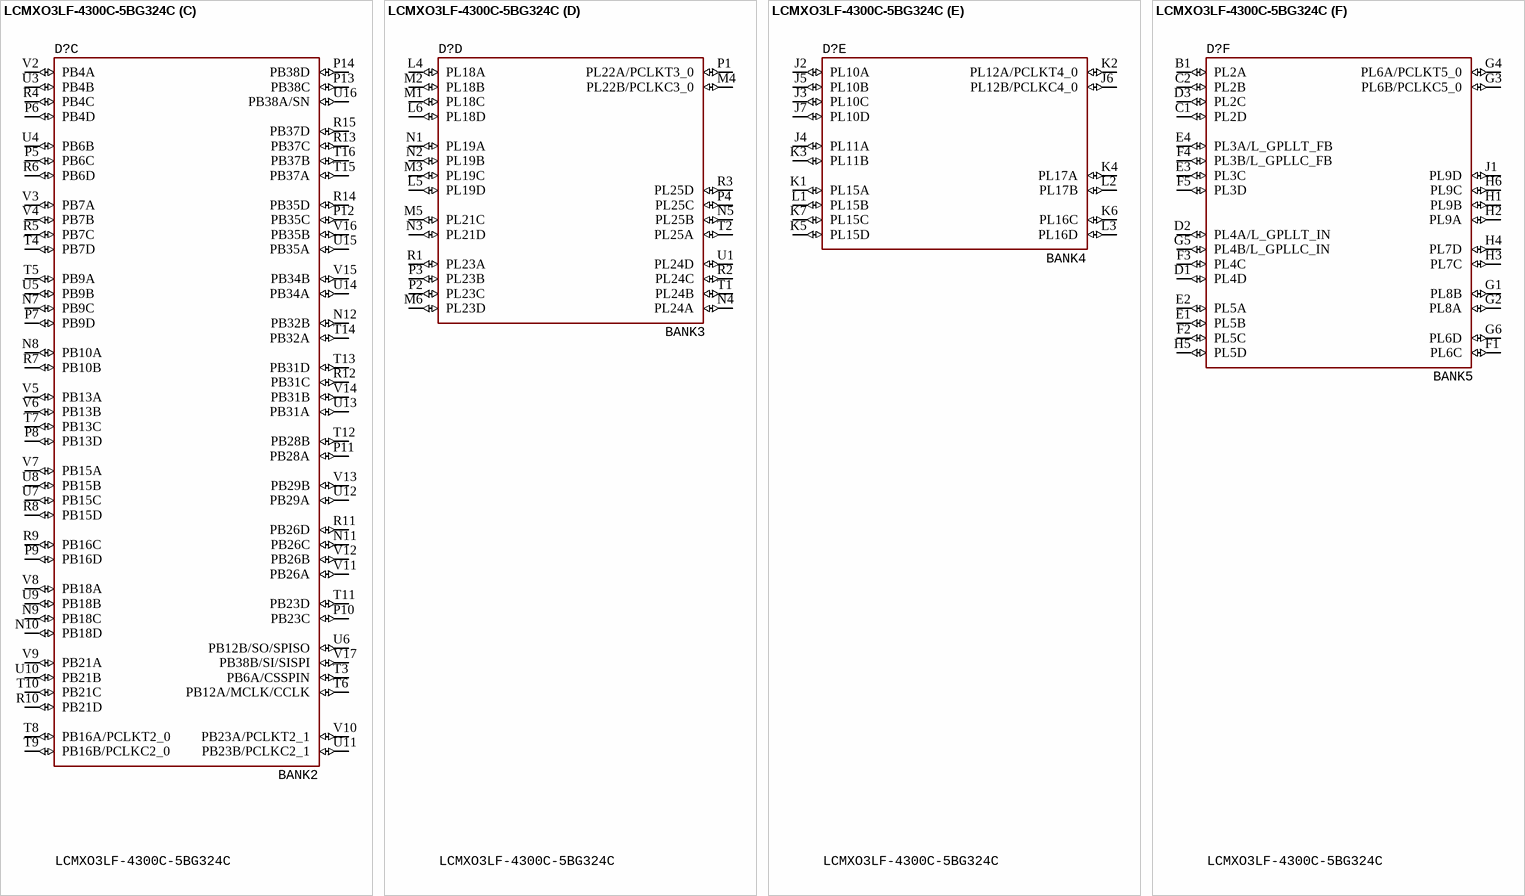
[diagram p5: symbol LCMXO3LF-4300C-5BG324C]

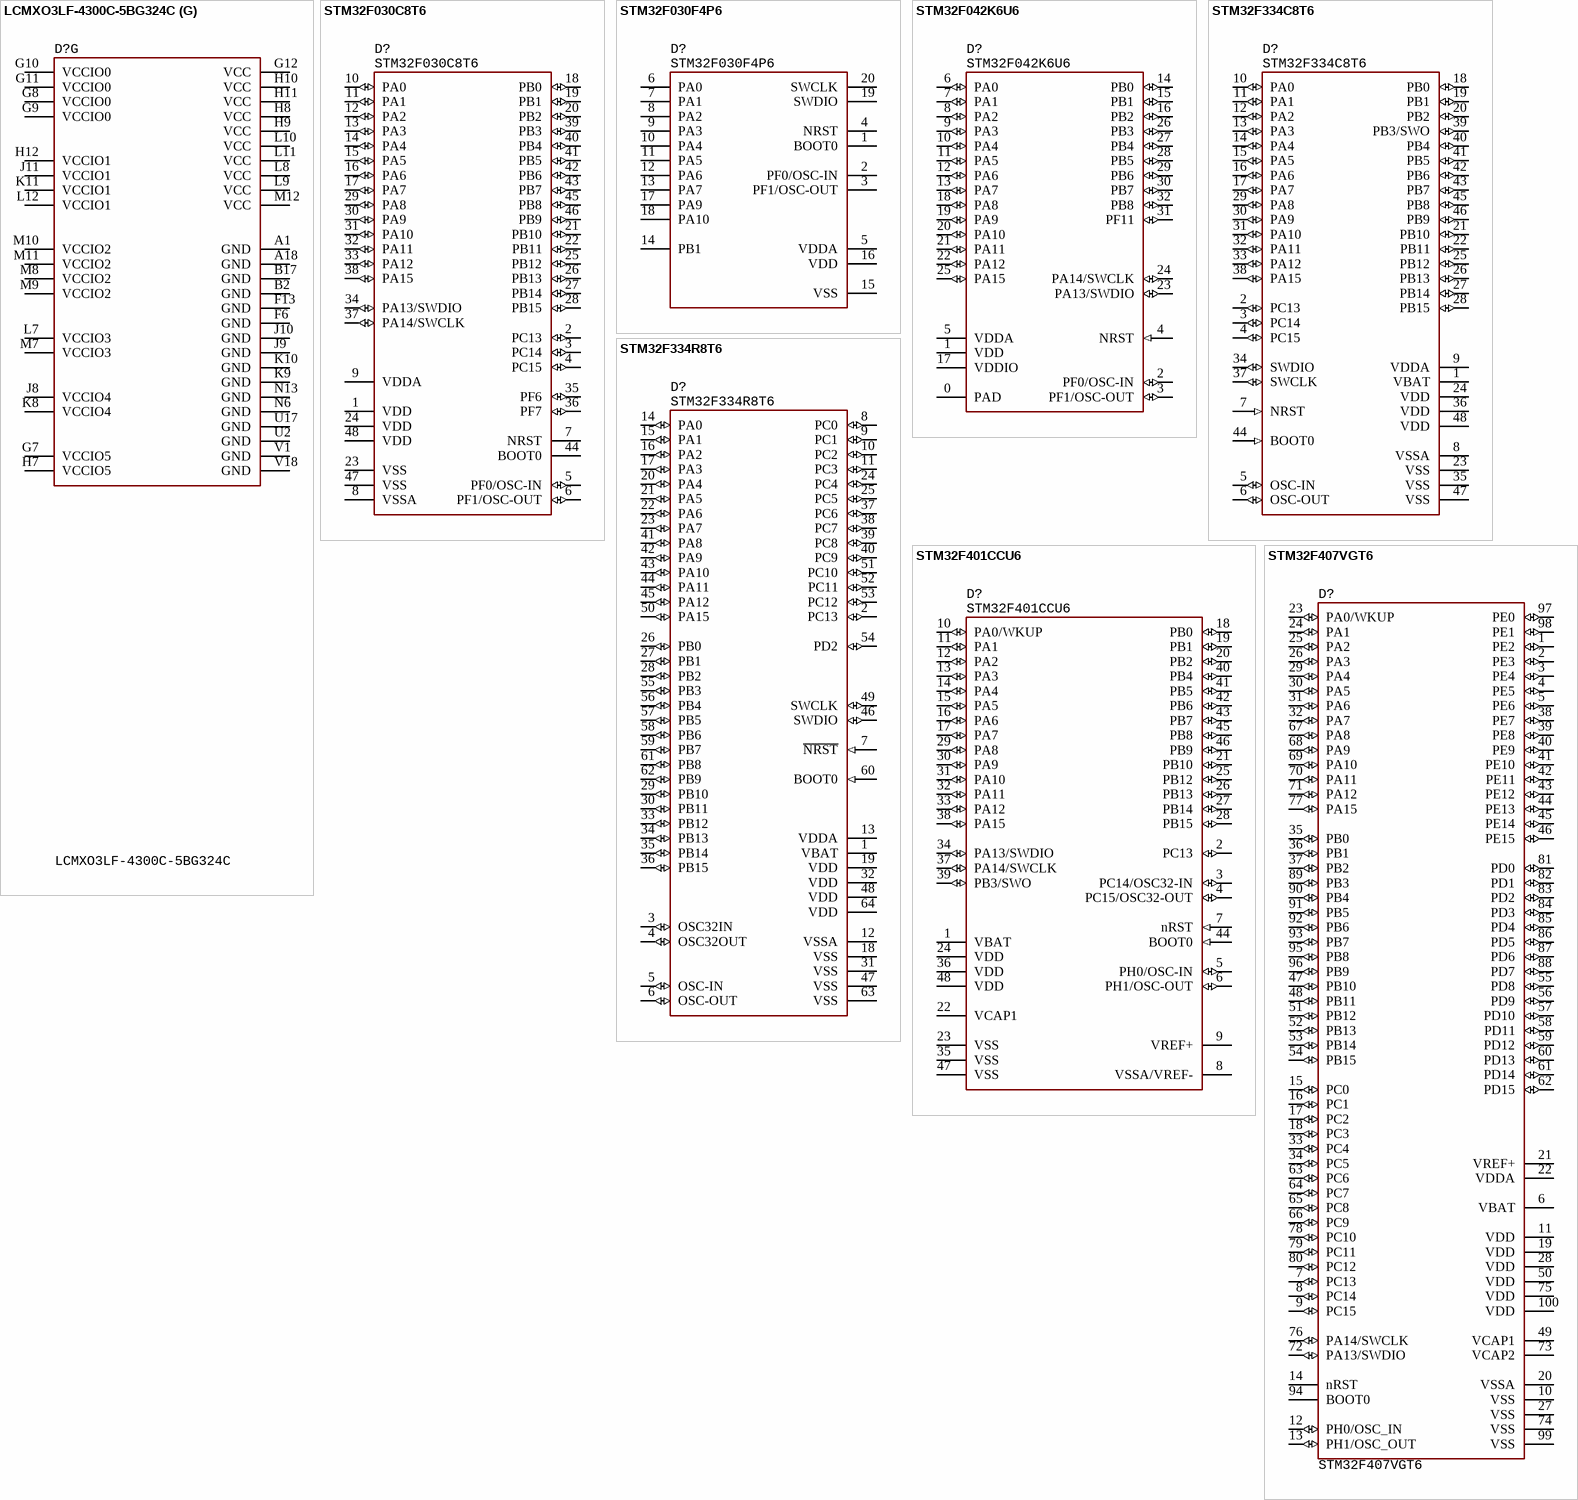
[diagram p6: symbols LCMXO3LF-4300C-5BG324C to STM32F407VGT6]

## LCMXO3LF-4300C-5BG324C
designator D?
FPGA, 4300LE, 92kbit, 400MHz, 279I/O, supply 2.5/3.3V, caBGA-324, 0...+85°C; Manufacturer: Lattice; Manufacturer: Lattice Semiconductor
footprint 324-BGA (15x15, pitch 0.8) (Pitch 0.8 mm)
part A pins: A2 PT9A (io), A3 PT11A (io), A4 PT12A (io), A5 PT12B (io), A6 PT14B (io), A7 PT15A (io), A8 PT17B (io), A9 PT18A/PCLKT0_1 (io), A10 PT21A (io), A11 PT26A (io), A12 PT26B (io), A13 PT28A (io), A14 PT28B (io), A15 PT35A (io), A16 PT35B (io), A17 PT36B (io), B3 PT9B (io), B4 PT11B (io), B5 PT11D (io), B6 PT14A (io), B7 PT15B (io), B8 PT17A (io), B9 PT18B/PCLKC0_1 (io), B10 PT21B (io), B11 PT22B (io), B12 PT25A (io), B13 PT27B (io), B14 PT33A (io), B15 PT33B (io), B16 PT36A (io), C3 PT10A (io), C4 PT10B (io), C5 PT13A (io), C6 PT14D/TDI (io), C7 PT17C/TCK (io), C8 PT17D/TMS (io), C9 PT21C (io), C10 PT22A (io), C11 PT25B (io), C12 PT27A (io), C13 PT32B (io), C14 PT34A (io), C15 PT34B (io), C16 PT36C/INITN (io), D4 PT9C (io), D5 PT11C (io), D6 PT13B (io), D7 PT14C/TDO (io), D8 PT16A (io), D9 PT21D (io), D10 PT22D/SDA/PCLKC0_0 (io), D11 PT27C/JTAGENB (io), D12 PT27D/PROGRAMN (io), D13 PT34C (io), D14 PT35C (io), D15 PT35D (io), E5 PT9D (io), E6 PT10D (io), E7 PT16B (io), E8 PT18C (io), E9 PT22C/SCL/PCLKT0_0 (io), E10 PT26C (io), E11 PT26D (io), E12 PT33C (io), E13 PT34D (io), E14 PT36D/DONE (io), F7 PT10C (io), F8 PT18D (io), F9 PT25C (io), F10 PT25D (io), F11 PT32A (io), F12 PT33D (io)
part B pins: B18 PR2A/R_GPLLT_FB (io), C17 PR2B/R_GPLLC_FB (io), C18 PR3B/R_GPLLC_IN (io), D16 PR2D (io), D17 PR4B (io), D18 PR6D (io), E15 PR3A/R_GPLLT_IN (io), E16 PR4C (io), E17 PR6C (io), E18 PR8A (io), F14 PR2C (io), F15 PR4A (io), F16 PR5B (io), F17 PR7D (io), F18 PR8D (io), G13 PR3C (io), G14 PR3D (io), G15 PR5A (io), G16 PR7A (io), G17 PR8B (io), G18 PR10D (io), H13 PR4D (io), H14 PR7C (io), H15 PR7B (io), H16 PR8C (io), H17 PR9B (io), H18 PR12A/PCLKT1_0 (io), J12 PR11D (io), J13 PR10C (io), J14 PR11C (io), J15 PR9A (io), J16 PR11A (io), J17 PR11B (io), J18 PR15B (io), K12 PR16C (io), K13 PR16D (io), K14 PR15A (io), K15 PR12B/PCLKC1_0 (io), K16 PR16A (io), K17 PR16B (io), K18 PR17A (io), L13 PR17D (io), L14 PR21C (io), L15 PR17C (io), L16 PR17B (io), L17 PR18A (io), L18 PR19C (io), M13 PR23D (io), M14 PR22C (io), M15 PR22A (io), M16 PR18B (io), M17 PR21A (io), M18 PR19D (io), N14 PR24D (io), N15 PR23B (io), N16 PR22D (io), N17 PR21D (io), N18 PR21B (io), P15 PR25A (io), P16 PR24A (io), P17 PR23A (io), P18 PR22B (io), R16 PR25C (io), R17 PR24C (io), R18 PR23C (io), T17 PR25D (io), T18 PR24B (io), U18 PR25B (io)
part C pins: N7 PB9C (io), N8 PB10A (io), N9 PB18C (io), N10 PB18D (io), N11 PB26C (io), N12 PB32B (io), P5 PB6C (io), P6 PB4D (io), P7 PB9D (io), P8 PB13D (io), P9 PB16D (io), P10 PB23C (io), P11 PB28A (io), P12 PB35C (io), P13 PB38C (io), P14 PB38D (io), R4 PB4C (io), R5 PB7C (io), R6 PB6D (io), R7 PB10B (io), R8 PB15D (io), R9 PB16C (io), R10 PB21D (io), R11 PB26D (io), R12 PB31C (io), R13 PB37C (io), R14 PB35D (io), R15 PB37D (io), T3 PB6A/CSSPIN (io), T4 PB7D (io), T5 PB9A (io), T6 PB12A/MCLK/CCLK (io), T7 PB13C (io), T8 PB16A/PCLKT2_0 (io), T9 PB16B/PCLKC2_0 (io), T10 PB21C (io), T11 PB23D (io), T12 PB28B (io), T13 PB31D (io), T14 PB32A (io), T15 PB37A (io), T16 PB37B (io), U3 PB4B (io), U4 PB6B (io), U5 PB9B (io), U6 PB12B/SO/SPISO (io), U7 PB15C (io), U8 PB15B (io), U9 PB18B (io), U10 PB21B (io), U11 PB23B/PCLKC2_1 (io), U12 PB29A (io), U13 PB31A (io), U14 PB34A (io), U15 PB35A (io), U16 PB38A/SN (io), V2 PB4A (io), V3 PB7A (io), V4 PB7B (io), V5 PB13A (io), V6 PB13B (io), V7 PB15A (io), V8 PB18A (io), V9 PB21A (io), V10 PB23A/PCLKT2_1 (io), V11 PB26A (io), V12 PB26B (io), V13 PB29B (io), V14 PB31B (io), V15 PB34B (io), V16 PB35B (io), V17 PB38B/SI/SISPI (io)
part D pins: L4 PL18A (io), L5 PL19D (io), L6 PL18D (io), M1 PL18C (io), M2 PL18B (io), M3 PL19C (io), M4 PL22B/PCLKC3_0 (io), M5 PL21C (io), M6 PL23D (io), N1 PL19A (io), N2 PL19B (io), N3 PL21D (io), N4 PL24A (io), N5 PL25B (io), P1 PL22A/PCLKT3_0 (io), P2 PL23C (io), P3 PL23B (io), P4 PL25C (io), R1 PL23A (io), R2 PL24C (io), R3 PL25D (io), T1 PL24B (io), T2 PL25A (io), U1 PL24D (io)
part E pins: J2 PL10A (io), J3 PL10C (io), J4 PL11A (io), J5 PL10B (io), J6 PL12B/PCLKC4_0 (io), J7 PL10D (io), K1 PL15A (io), K2 PL12A/PCLKT4_0 (io), K3 PL11B (io), K4 PL17A (io), K5 PL15D (io), K6 PL16C (io), K7 PL15C (io), L1 PL15B (io), L2 PL17B (io), L3 PL16D (io)
part F pins: B1 PL2A (io), C1 PL2D (io), C2 PL2B (io), D1 PL4D (io), D2 PL4A/L_GPLLT_IN (io), D3 PL2C (io), E1 PL5B (io), E2 PL5A (io), E3 PL3C (io), E4 PL3A/L_GPLLT_FB (io), F1 PL6C (io), F2 PL5C (io), F3 PL4C (io), F4 PL3B/L_GPLLC_FB (io), F5 PL3D (io), G1 PL8B (io), G2 PL8A (io), G3 PL6B/PCLKC5_0 (io), G4 PL6A/PCLKT5_0 (io), G5 PL4B/L_GPLLC_IN (io), G6 PL6D (io), H1 PL9B (io), H2 PL9A (io), H3 PL7C (io), H4 PL7D (io), H5 PL5D (io), H6 PL9C (io), J1 PL9D (io)
part G pins: A1 GND (power), A18 GND (power), B2 GND (power), B17 GND (power), F6 GND (power), F13 GND (power), G7 VCCIO5 (power), G8 VCCIO0 (power), G9 VCCIO0 (power), G10 VCCIO0 (power), G11 VCCIO0 (power), G12 VCC (power), H7 VCCIO5 (power), H8 VCC (power), H9 VCC (power), H10 VCC (power), H11 VCC (power), H12 VCCIO1 (power), J8 VCCIO4 (power), J9 GND (power), J10 GND (power), J11 VCCIO1 (power), K8 VCCIO4 (power), K9 GND (power), K10 GND (power), K11 VCCIO1 (power), L7 VCCIO3 (power), L8 VCC (power), L9 VCC (power), L10 VCC (power), L11 VCC (power), L12 VCCIO1 (power), M7 VCCIO3 (power), M8 VCCIO2 (power), M9 VCCIO2 (power), M10 VCCIO2 (power), M11 VCCIO2 (power), M12 VCC (power), N6 GND (power), N13 GND (power), U2 GND (power), U17 GND (power), V1 GND (power), V18 GND (power)

## STM32F030C8T6
designator D?
Cortex-M0, 48MHz, 64KB ROM, 8KB RAM, 1.8...3.6V, LQFP-48, -40...+85°C; Manufacturer: STMicroelectronics
footprint 48-LQFP (QFP, 48-Leads, Body 7x7mm, Pitch 0.5mm, IPC Medium Density)
pins: 1 VDD, 2 PC13 (io), 3 PC14 (io), 4 PC15 (io), 5 PF0/OSC-IN (io), 6 PF1/OSC-OUT (io), 7 NRST, 8 VSSA, 9 VDDA, 10 PA0 (io), 11 PA1 (io), 12 PA2 (io), 13 PA3 (io), 14 PA4 (io), 15 PA5 (io), 16 PA6 (io), 17 PA7 (io), 18 PB0 (io), 19 PB1 (io), 20 PB2 (io), 21 PB10 (io), 22 PB11 (io), 23 VSS, 24 VDD, 25 PB12 (io), 26 PB13 (io), 27 PB14 (io), 28 PB15 (io), 29 PA8 (io), 30 PA9 (io), 31 PA10 (io), 32 PA11 (io), 33 PA12 (io), 34 PA13/SWDIO (io), 35 PF6 (io), 36 PF7 (io), 37 PA14/SWCLK (io), 38 PA15 (io), 39 PB3 (io), 40 PB4 (io), 41 PB5 (io), 42 PB6 (io), 43 PB7 (io), 44 BOOT0, 45 PB8 (io), 46 PB9 (io), 47 VSS, 48 VDD

## STM32F030F4P6
designator D?
Cortex-M0, 48MHz, 16KB ROM, 4KB RAM, 2.4...3.6V, TSSOP-20, -40...+85°C; Manufacturer: STMicroelectronics
footprint 20-TSSOP (pitch 0.65 mm)
pins: 1 BOOT0, 2 PF0/OSC-IN, 3 PF1/OSC-OUT, 4 NRST, 5 VDDA, 6 PA0, 7 PA1, 8 PA2, 9 PA3, 10 PA4, 11 PA5, 12 PA6, 13 PA7, 14 PB1, 15 VSS, 16 VDD, 17 PA9, 18 PA10, 19 SWDIO, 20 SWCLK

## STM32F042K6U6
designator D?
Cortex-M0, 48MHz, 32KB ROM, 6KB RAM, 2.4...3.6V, QFN-32, -40...+85°C; Manufacturer: STMicroelectronics
footprint 32-QFN (5x5, pitch 0.5) (5x5 mm, pitch 0.5 mm, power pad)
pins: 0 PAD, 1 VDD, 2 PF0/OSC-IN (io), 3 PF1/OSC-OUT (io), 4 NRST (in), 5 VDDA, 6 PA0 (io), 7 PA1 (io), 8 PA2 (io), 9 PA3 (io), 10 PA4 (io), 11 PA5 (io), 12 PA6 (io), 13 PA7 (io), 14 PB0 (io), 15 PB1 (io), 16 PB2 (io), 17 VDDIO, 18 PA8 (io), 19 PA9 (io), 20 PA10 (io), 21 PA11 (io), 22 PA12 (io), 23 PA13/SWDIO (io), 24 PA14/SWCLK (io), 25 PA15 (io), 26 PB3 (io), 27 PB4 (io), 28 PB5 (io), 29 PB6 (io), 30 PB7 (io), 31 PF11 (io), 32 PB8 (io)

## STM32F334C8T6
designator D?
Cortex-M4, 72MHz, 64KB ROM, 12KB RAM, 2...3.6V, LQFP-48, -40...+85°C; Manufacturer: STMicroelectronics
footprint 48-LQFP (QFP, 48-Leads, Body 7x7mm, Pitch 0.5mm, IPC Medium Density)
pins: 1 VBAT, 2 PC13 (io), 3 PC14 (io), 4 PC15 (io), 5 OSC-IN (io), 6 OSC-OUT (io), 7 NRST (in), 8 VSSA, 9 VDDA, 10 PA0 (io), 11 PA1 (io), 12 PA2 (io), 13 PA3 (io), 14 PA4 (io), 15 PA5 (io), 16 PA6 (io), 17 PA7 (io), 18 PB0 (io), 19 PB1 (io), 20 PB2 (io), 21 PB10 (io), 22 PB11 (io), 23 VSS, 24 VDD, 25 PB12 (io), 26 PB13 (io), 27 PB14 (io), 28 PB15 (io), 29 PA8 (io), 30 PA9 (io), 31 PA10 (io), 32 PA11 (io), 33 PA12 (io), 34 SWDIO (io), 35 VSS, 36 VDD, 37 SWCLK (io), 38 PA15 (io), 39 PB3/SWO (io), 40 PB4 (io), 41 PB5 (io), 42 PB6 (io), 43 PB7 (io), 44 BOOT0 (in), 45 PB8 (io), 46 PB9 (io), 47 VSS, 48 VDD

## STM32F334R8T6
designator D?
Cortex-M4, 72MHz, 64KB ROM, 12KB RAM, 2...3.6V, LQFP-64, -40...+85°C; Manufacturer: STMicroelectronics
footprint 64-LQFP (Thin QFP, 64-Leads, Body 10x10mm, Pitch 0.5mm, IPC Medium Density)
pins: 1 VBAT (power), 2 PC13 (io), 3 OSC32IN (io), 4 OSC32OUT (io), 5 OSC-IN (io), 6 OSC-OUT (io), 7 ~{NRST} (in), 8 PC0 (io), 9 PC1 (io), 10 PC2 (io), 11 PC3 (io), 12 VSSA (power), 13 VDDA (power), 14 PA0 (io), 15 PA1 (io), 16 PA2 (io), 17 PA3 (io), 18 VSS (power), 19 VDD (power), 20 PA4 (io), 21 PA5 (io), 22 PA6 (io), 23 PA7 (io), 24 PC4 (io), 25 PC5 (io), 26 PB0 (io), 27 PB1 (io), 28 PB2 (io), 29 PB10 (io), 30 PB11 (io), 31 VSS (power), 32 VDD (power), 33 PB12 (io), 34 PB13 (io), 35 PB14 (io), 36 PB15 (io), 37 PC6 (io), 38 PC7 (io), 39 PC8 (io), 40 PC9 (io), 41 PA8 (io), 42 PA9 (io), 43 PA10 (io), 44 PA11 (io), 45 PA12 (io), 46 SWDIO (io), 47 VSS (power), 48 VDD (power), 49 SWCLK (io), 50 PA15 (io), 51 PC10 (io), 52 PC11 (io), 53 PC12 (io), 54 PD2 (io), 55 PB3 (io), 56 PB4 (io), 57 PB5 (io), 58 PB6 (io), 59 PB7 (io), 60 BOOT0 (in), 61 PB8 (io), 62 PB9 (io), 63 VSS (power), 64 VDD (power)

## STM32F401CCU6
designator D?
Cortex-M4, 84MHz, 256KB ROM, 64KB RAM, 1.7...3.6V, QFN-48, -40...+85°C; Manufacturer: STMicroelectronics
footprint 48-QFN (7x7, pitch 0.5) (7x7 mm, pitch 0.5 mm, power pad)
pins: 1 VBAT, 2 PC13 (io), 3 PC14/OSC32-IN (io), 4 PC15/OSC32-OUT (io), 5 PH0/OSC-IN (io), 6 PH1/OSC-OUT (io), 7 nRST (in), 8 VSSA/VREF-, 9 VREF+, 10 PA0/WKUP (io), 11 PA1 (io), 12 PA2 (io), 13 PA3 (io), 14 PA4 (io), 15 PA5 (io), 16 PA6 (io), 17 PA7 (io), 18 PB0 (io), 19 PB1 (io), 20 PB2 (io), 21 PB10 (io), 22 VCAP1, 23 VSS, 24 VDD, 25 PB12 (io), 26 PB13 (io), 27 PB14 (io), 28 PB15 (io), 29 PA8 (io), 30 PA9 (io), 31 PA10 (io), 32 PA11 (io), 33 PA12 (io), 34 PA13/SWDIO (io), 35 VSS, 36 VDD, 37 PA14/SWCLK (io), 38 PA15 (io), 39 PB3/SWO (io), 40 PB4 (io), 41 PB5 (io), 42 PB6 (io), 43 PB7 (io), 44 BOOT0 (in), 45 PB8 (io), 46 PB9 (io), 47 VSS, 48 VDD

## STM32F407VGT6
designator D?  PartNumber: STM32F407VGT6
Cortex-M4, 168MHz, 1024KB ROM, 192KB RAM, 1.8...3.6V, LQFP-100, -40...+85°C; Manufacturer: STMicroelectronics
footprint 100-LQFP (Thin QFP, 100-Leads, Body 14x14mm, Pitch 0.5mm, IPC Medium Density)
pins: 1 PE2 (io), 2 PE3 (io), 3 PE4 (io), 4 PE5 (io), 5 PE6 (io), 6 VBAT, 7 PC13 (io), 8 PC14 (io), 9 PC15 (io), 10 VSS, 11 VDD, 12 PH0/OSC_IN (io), 13 PH1/OSC_OUT (io), 14 nRST, 15 PC0 (io), 16 PC1 (io), 17 PC2 (io), 18 PC3 (io), 19 VDD, 20 VSSA, 21 VREF+, 22 VDDA, 23 PA0/WKUP (io), 24 PA1 (io), 25 PA2 (io), 26 PA3 (io), 27 VSS, 28 VDD, 29 PA4 (io), 30 PA5 (io), 31 PA6 (io), 32 PA7 (io), 33 PC4 (io), 34 PC5 (io), 35 PB0 (io), 36 PB1 (io), 37 PB2 (io), 38 PE7 (io), 39 PE8 (io), 40 PE9 (io), 41 PE10 (io), 42 PE11 (io), 43 PE12 (io), 44 PE13 (io), 45 PE14 (io), 46 PE15 (io), 47 PB10 (io), 48 PB11 (io), 49 VCAP1, 50 VDD, 51 PB12 (io), 52 PB13 (io), 53 PB14 (io), 54 PB15 (io), 55 PD8 (io), 56 PD9 (io), 57 PD10 (io), 58 PD11 (io), 59 PD12 (io), 60 PD13 (io), 61 PD14 (io), 62 PD15 (io), 63 PC6 (io), 64 PC7 (io), 65 PC8 (io), 66 PC9 (io), 67 PA8 (io), 68 PA9 (io), 69 PA10 (io), 70 PA11 (io), 71 PA12 (io), 72 PA13/SWDIO (io), 73 VCAP2, 74 VSS, 75 VDD, 76 PA14/SWCLK (io), 77 PA15 (io), 78 PC10 (io), 79 PC11 (io), 80 PC12 (io), 81 PD0 (io), 82 PD1 (io), 83 PD2 (io), 84 PD3 (io), 85 PD4 (io), 86 PD5 (io), 87 PD6 (io), 88 PD7 (io), 89 PB3 (io), 90 PB4 (io), 91 PB5 (io), 92 PB6 (io), 93 PB7 (io), 94 BOOT0, 95 PB8 (io), 96 PB9 (io), 97 PE0 (io), 98 PE1 (io), 99 VSS, 100 VDD

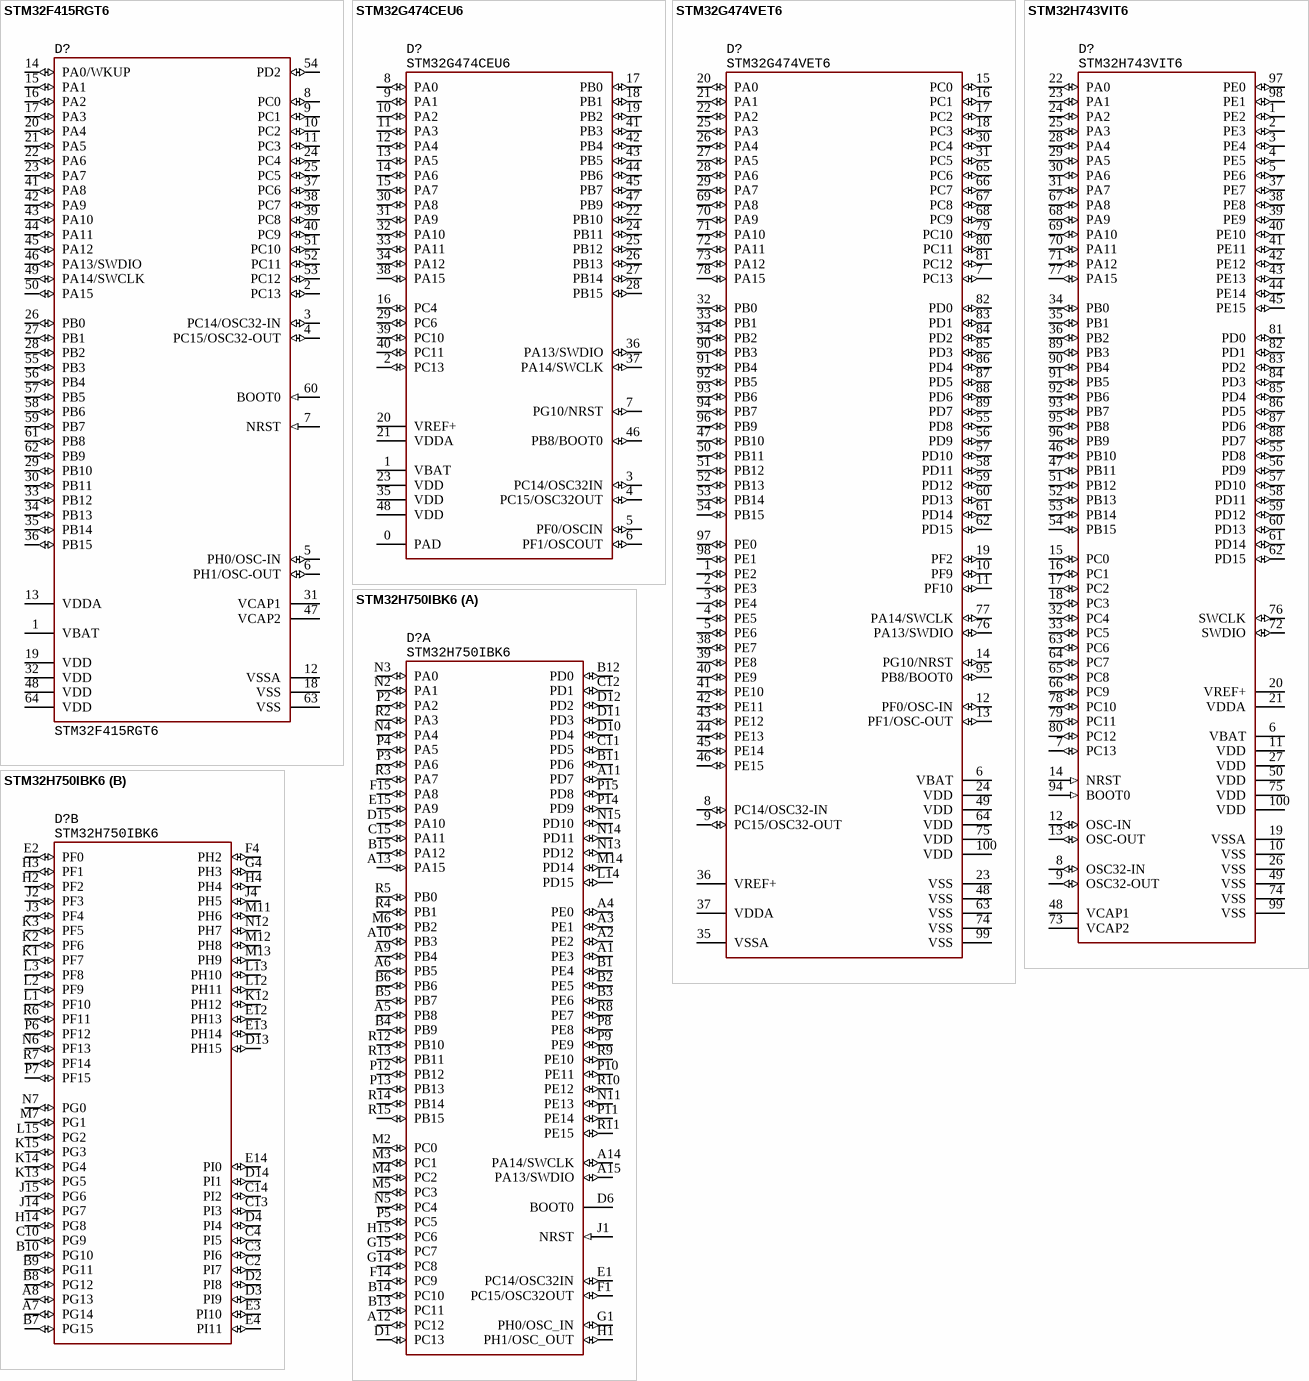
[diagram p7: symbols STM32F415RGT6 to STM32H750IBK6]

## STM32F415RGT6
designator D?  PartNumber: STM32F415RGT6
Cortex-M4, 168MHz, 1024KB ROM, 192KB RAM, 1.8...3.6V, LQFP-64, -40...+85°C; Manufacturer: STMicroelectronics
footprint 64-LQFP (Thin QFP, 64-Leads, Body 10x10mm, Pitch 0.5mm, IPC Medium Density)
pins: 1 VBAT, 2 PC13 (io), 3 PC14/OSC32-IN (io), 4 PC15/OSC32-OUT (io), 5 PH0/OSC-IN (io), 6 PH1/OSC-OUT (io), 7 NRST (in), 8 PC0 (io), 9 PC1 (io), 10 PC2 (io), 11 PC3 (io), 12 VSSA, 13 VDDA, 14 PA0/WKUP (io), 15 PA1 (io), 16 PA2 (io), 17 PA3 (io), 18 VSS, 19 VDD, 20 PA4 (io), 21 PA5 (io), 22 PA6 (io), 23 PA7 (io), 24 PC4 (io), 25 PC5 (io), 26 PB0 (io), 27 PB1 (io), 28 PB2 (io), 29 PB10 (io), 30 PB11 (io), 31 VCAP1, 32 VDD, 33 PB12 (io), 34 PB13 (io), 35 PB14 (io), 36 PB15 (io), 37 PC6 (io), 38 PC7 (io), 39 PC8 (io), 40 PC9 (io), 41 PA8 (io), 42 PA9 (io), 43 PA10 (io), 44 PA11 (io), 45 PA12 (io), 46 PA13/SWDIO (io), 47 VCAP2, 48 VDD, 49 PA14/SWCLK (io), 50 PA15 (io), 51 PC10 (io), 52 PC11 (io), 53 PC12 (io), 54 PD2 (io), 55 PB3 (io), 56 PB4 (io), 57 PB5 (io), 58 PB6 (io), 59 PB7 (io), 60 BOOT0 (in), 61 PB8 (io), 62 PB9 (io), 63 VSS, 64 VDD

## STM32G474CEU6
designator D?
Cortex-M4, 170MHz, 512KB ROM, 128KB RAM, 1.71...3.6V, QFN-48, -40...+85°C; Manufacturer: STMicroelectronics
footprint 48-QFN (7x7, pitch 0.5) (7x7 mm, pitch 0.5 mm, power pad)
pins: 0 PAD, 1 VBAT, 2 PC13 (io), 3 PC14/OSC32IN (io), 4 PC15/OSC32OUT (io), 5 PF0/OSCIN (io), 6 PF1/OSCOUT (io), 7 PG10/NRST (io), 8 PA0 (io), 9 PA1 (io), 10 PA2 (io), 11 PA3 (io), 12 PA4 (io), 13 PA5 (io), 14 PA6 (io), 15 PA7 (io), 16 PC4 (io), 17 PB0 (io), 18 PB1 (io), 19 PB2 (io), 20 VREF+, 21 VDDA, 22 PB10 (io), 23 VDD, 24 PB11 (io), 25 PB12 (io), 26 PB13 (io), 27 PB14 (io), 28 PB15 (io), 29 PC6 (io), 30 PA8 (io), 31 PA9 (io), 32 PA10 (io), 33 PA11 (io), 34 PA12 (io), 35 VDD, 36 PA13/SWDIO (io), 37 PA14/SWCLK (io), 38 PA15 (io), 39 PC10 (io), 40 PC11 (io), 41 PB3 (io), 42 PB4 (io), 43 PB5 (io), 44 PB6 (io), 45 PB7 (io), 46 PB8/BOOT0 (io), 47 PB9 (io), 48 VDD

## STM32G474VET6
designator D?
Cortex-M4, 170MHz, 512KB ROM, 128KB RAM, 1.71...3.6V, LQFP-100, -40...+85°C; Manufacturer: STMicroelectronics
footprint 100-LQFP (Thin QFP, 100-Leads, Body 14x14mm, Pitch 0.5mm, IPC Medium Density)
pins: 1 PE2 (io), 2 PE3 (io), 3 PE4 (io), 4 PE5 (io), 5 PE6 (io), 6 VBAT, 7 PC13 (io), 8 PC14/OSC32-IN (io), 9 PC15/OSC32-OUT (io), 10 PF9 (io), 11 PF10 (io), 12 PF0/OSC-IN (io), 13 PF1/OSC-OUT (io), 14 PG10/NRST (io), 15 PC0 (io), 16 PC1 (io), 17 PC2 (io), 18 PC3 (io), 19 PF2 (io), 20 PA0 (io), 21 PA1 (io), 22 PA2 (io), 23 VSS, 24 VDD, 25 PA3 (io), 26 PA4 (io), 27 PA5 (io), 28 PA6 (io), 29 PA7 (io), 30 PC4 (io), 31 PC5 (io), 32 PB0 (io), 33 PB1 (io), 34 PB2 (io), 35 VSSA, 36 VREF+, 37 VDDA, 38 PE7 (io), 39 PE8 (io), 40 PE9 (io), 41 PE10 (io), 42 PE11 (io), 43 PE12 (io), 44 PE13 (io), 45 PE14 (io), 46 PE15 (io), 47 PB10 (io), 48 VSS, 49 VDD, 50 PB11 (io), 51 PB12 (io), 52 PB13 (io), 53 PB14 (io), 54 PB15 (io), 55 PD8 (io), 56 PD9 (io), 57 PD10 (io), 58 PD11 (io), 59 PD12 (io), 60 PD13 (io), 61 PD14 (io), 62 PD15 (io), 63 VSS, 64 VDD, 65 PC6 (io), 66 PC7 (io), 67 PC8 (io), 68 PC9 (io), 69 PA8 (io), 70 PA9 (io), 71 PA10 (io), 72 PA11 (io), 73 PA12 (io), 74 VSS, 75 VDD, 76 PA13/SWDIO (io), 77 PA14/SWCLK (io), 78 PA15 (io), 79 PC10 (io), 80 PC11 (io), 81 PC12 (io), 82 PD0 (io), 83 PD1 (io), 84 PD2 (io), 85 PD3 (io), 86 PD4 (io), 87 PD5 (io), 88 PD6 (io), 89 PD7 (io), 90 PB3 (io), 91 PB4 (io), 92 PB5 (io), 93 PB6 (io), 94 PB7 (io), 95 PB8/BOOT0 (io), 96 PB9 (io), 97 PE0 (io), 98 PE1 (io), 99 VSS, 100 VDD

## STM32H743VIT6
designator D?
Cortex-M7, 480MHz, 2048KB ROM, 1024KB RAM, 1.71...3.6V, LQFP-100, -40...+85°C; Manufacturer: STMicroelectronics
footprint 100-LQFP (Thin QFP, 100-Leads, Body 14x14mm, Pitch 0.5mm, IPC Medium Density)
pins: 1 PE2 (io), 2 PE3 (io), 3 PE4 (io), 4 PE5 (io), 5 PE6 (io), 6 VBAT, 7 PC13 (io), 8 OSC32-IN (io), 9 OSC32-OUT (io), 10 VSS, 11 VDD, 12 OSC-IN (io), 13 OSC-OUT (io), 14 NRST (in), 15 PC0 (io), 16 PC1 (io), 17 PC2 (io), 18 PC3 (io), 19 VSSA, 20 VREF+, 21 VDDA, 22 PA0 (io), 23 PA1 (io), 24 PA2 (io), 25 PA3 (io), 26 VSS, 27 VDD, 28 PA4 (io), 29 PA5 (io), 30 PA6 (io), 31 PA7 (io), 32 PC4 (io), 33 PC5 (io), 34 PB0 (io), 35 PB1 (io), 36 PB2 (io), 37 PE7 (io), 38 PE8 (io), 39 PE9 (io), 40 PE10 (io), 41 PE11 (io), 42 PE12 (io), 43 PE13 (io), 44 PE14 (io), 45 PE15 (io), 46 PB10 (io), 47 PB11 (io), 48 VCAP1, 49 VSS, 50 VDD, 51 PB12 (io), 52 PB13 (io), 53 PB14 (io), 54 PB15 (io), 55 PD8 (io), 56 PD9 (io), 57 PD10 (io), 58 PD11 (io), 59 PD12 (io), 60 PD13 (io), 61 PD14 (io), 62 PD15 (io), 63 PC6 (io), 64 PC7 (io), 65 PC8 (io), 66 PC9 (io), 67 PA8 (io), 68 PA9 (io), 69 PA10 (io), 70 PA11 (io), 71 PA12 (io), 72 SWDIO (io), 73 VCAP2, 74 VSS, 75 VDD, 76 SWCLK (io), 77 PA15 (io), 78 PC10 (io), 79 PC11 (io), 80 PC12 (io), 81 PD0 (io), 82 PD1 (io), 83 PD2 (io), 84 PD3 (io), 85 PD4 (io), 86 PD5 (io), 87 PD6 (io), 88 PD7 (io), 89 PB3 (io), 90 PB4 (io), 91 PB5 (io), 92 PB6 (io), 93 PB7 (io), 94 BOOT0 (in), 95 PB8 (io), 96 PB9 (io), 97 PE0 (io), 98 PE1 (io), 99 VSS, 100 VDD

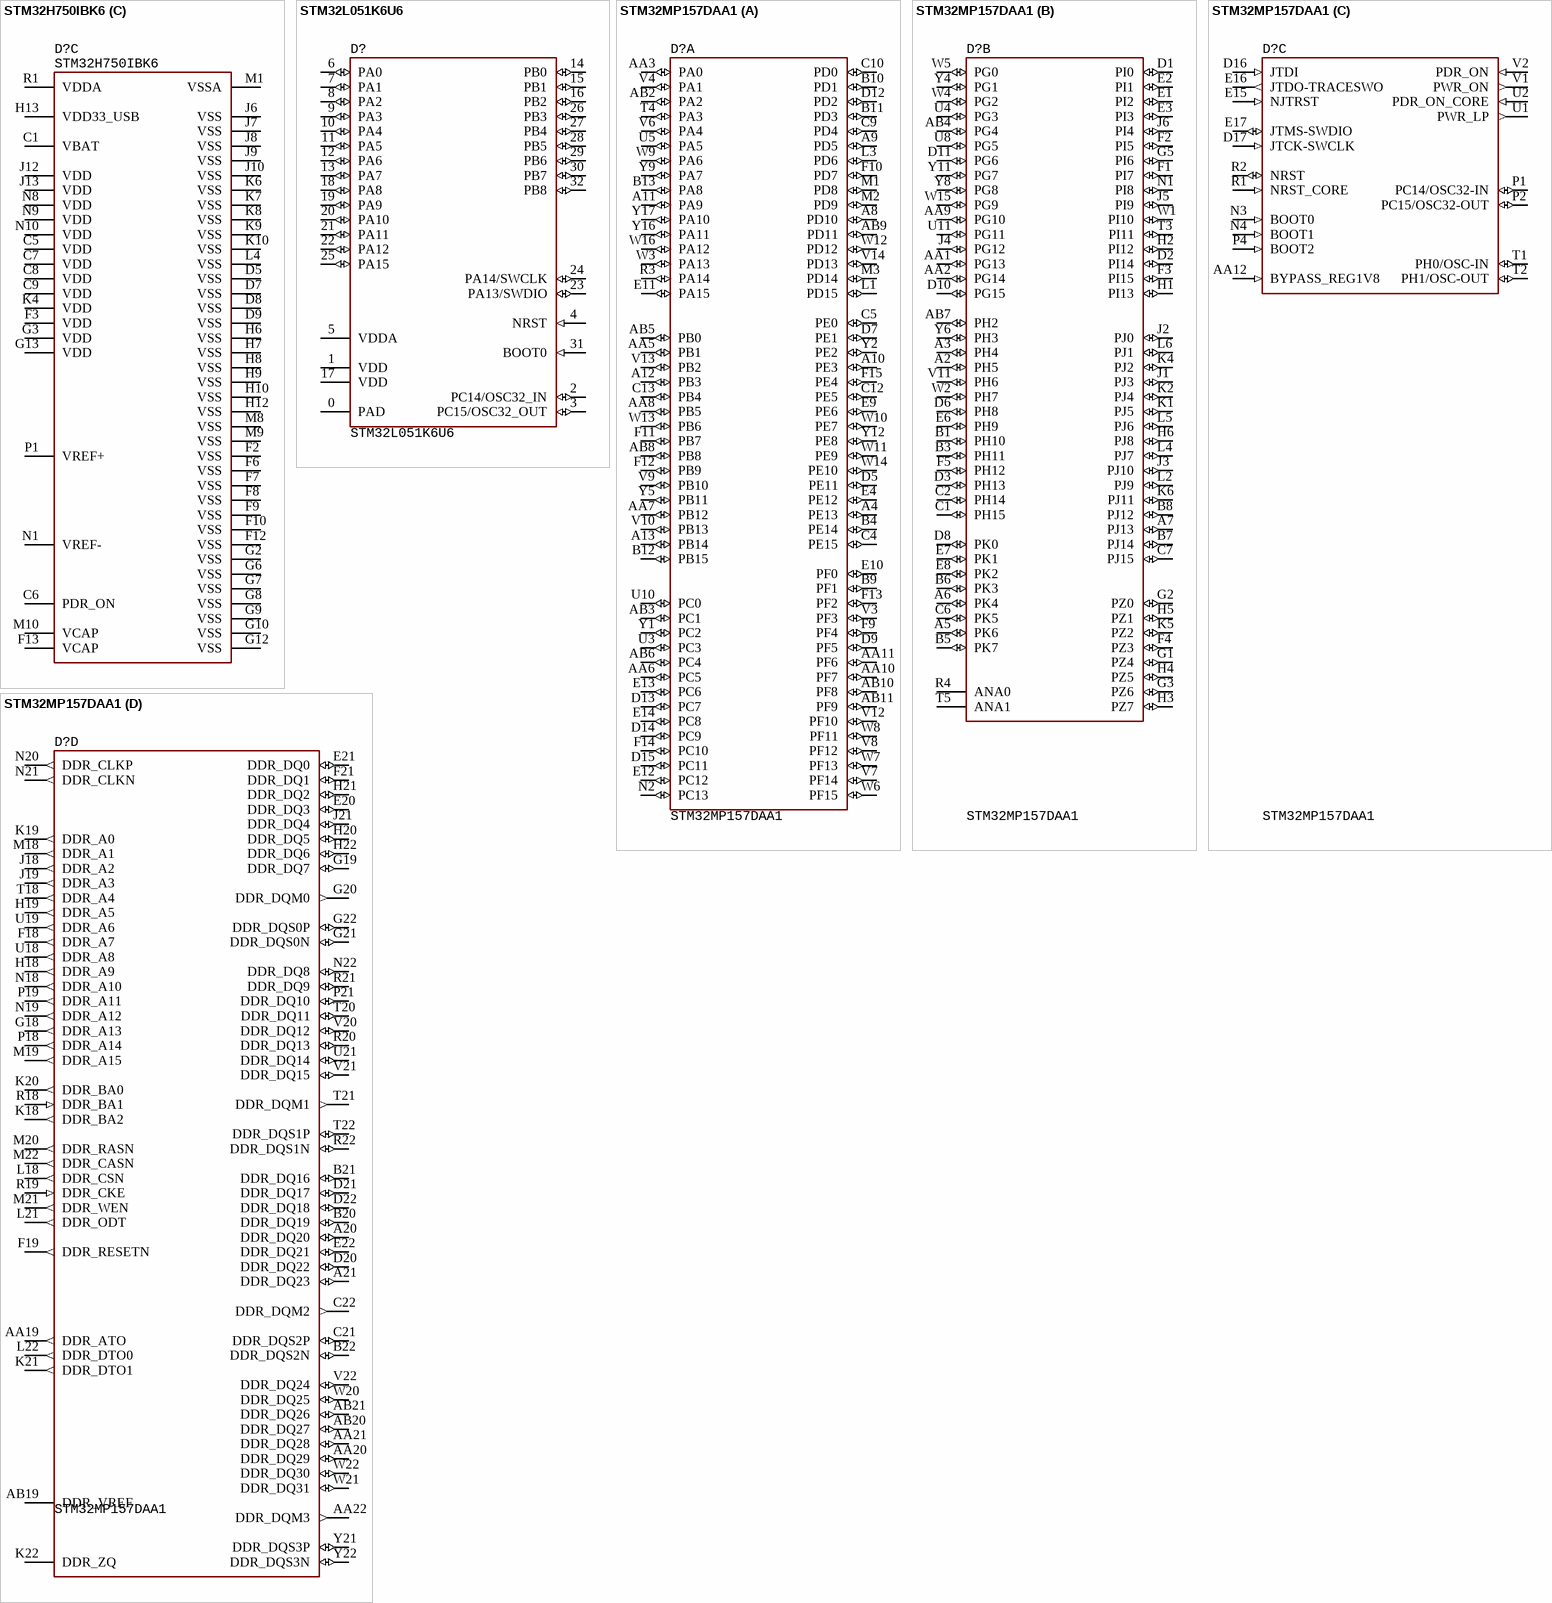
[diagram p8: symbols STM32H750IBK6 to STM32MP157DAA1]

## STM32H750IBK6
designator D?
Cortex-M7, 480MHz, 128KB ROM, 1024KB RAM, 1.62...3.6V, UFBGA-201, -40...+85°C; Manufacturer: STMicroelectronics
footprint 201-UFBGA (10x10, pitch 0.65)
part A pins: A1 PE3 (io), A2 PE2 (io), A3 PE1 (io), A4 PE0 (io), A5 PB8 (io), A6 PB5 (io), A9 PB4 (io), A10 PB3 (io), A11 PD7 (io), A12 PC12 (io), A13 PA15 (io), A14 PA14/SWCLK (io), A15 PA13/SWDIO (io), B1 PE4 (io), B2 PE5 (io), B3 PE6 (io), B4 PB9 (io), B5 PB7 (io), B6 PB6 (io), B11 PD6 (io), B12 PD0 (io), B13 PC11 (io), B14 PC10 (io), B15 PA12 (io), C11 PD5 (io), C12 PD1 (io), C15 PA11 (io), D1 PC13 (io), D6 BOOT0, D10 PD4 (io), D11 PD3 (io), D12 PD2 (io), D15 PA10 (io), E1 PC14/OSC32IN (io), E15 PA9 (io), F1 PC15/OSC32OUT (io), F14 PC9 (io), F15 PA8 (io), G1 PH0/OSC_IN (io), G14 PC8 (io), G15 PC7 (io), H1 PH1/OSC_OUT (io), H15 PC6 (io), J1 NRST (in), L14 PD15 (io), M2 PC0 (io), M3 PC1 (io), M4 PC2 (io), M5 PC3 (io), M6 PB2 (io), M14 PD14 (io), N2 PA1 (io), N3 PA0 (io), N4 PA4 (io), N5 PC4 (io), N11 PE13 (io), N13 PD12 (io), N14 PD11 (io), N15 PD10 (io), P2 PA2 (io), P3 PA6 (io), P4 PA5 (io), P5 PC5 (io), P8 PE8 (io), P9 PE9 (io), P10 PE11 (io), P11 PE14 (io), P12 PB12 (io), P13 PB13 (io), P14 PD9 (io), P15 PD8 (io), R2 PA3 (io), R3 PA7 (io), R4 PB1 (io), R5 PB0 (io), R8 PE7 (io), R9 PE10 (io), R10 PE12 (io), R11 PE15 (io), R12 PB10 (io), R13 PB11 (io), R14 PB14 (io), R15 PB15 (io)
part B pins: A7 PG14 (io), A8 PG13 (io), B7 PG15 (io), B8 PG12 (io), B9 PG11 (io), B10 PG10 (io), C2 PI7 (io), C3 PI6 (io), C4 PI5 (io), C10 PG9 (io), C13 PI3 (io), C14 PI2 (io), D2 PI8 (io), D3 PI9 (io), D4 PI4 (io), D13 PH15 (io), D14 PI1 (io), E2 PF0 (io), E3 PI10 (io), E4 PI11 (io), E12 PH13 (io), E13 PH14 (io), E14 PI0 (io), F4 PH2 (io), G4 PH3 (io), H2 PF2 (io), H3 PF1 (io), H4 PH4 (io), H14 PG8 (io), J2 PF3 (io), J3 PF4 (io), J4 PH5 (io), J14 PG7 (io), J15 PG6 (io), K1 PF7 (io), K2 PF6 (io), K3 PF5 (io), K12 PH12 (io), K13 PG5 (io), K14 PG4 (io), K15 PG3 (io), L1 PF10 (io), L2 PF9 (io), L3 PF8 (io), L12 PH11 (io), L13 PH10 (io), L15 PG2 (io), M7 PG1 (io), M11 PH6 (io), M12 PH8 (io), M13 PH9 (io), N6 PF13 (io), N7 PG0 (io), N12 PH7 (io), P6 PF12 (io), P7 PF15 (io), R6 PF11 (io), R7 PF14 (io)
part C pins: C1 VBAT, C5 VDD, C6 PDR_ON, C7 VDD, C8 VDD, C9 VDD, D5 VSS, D7 VSS, D8 VSS, D9 VSS, F2 VSS, F3 VDD, F6 VSS, F7 VSS, F8 VSS, F9 VSS, F10 VSS, F12 VSS, F13 VCAP, G2 VSS, G3 VDD, G6 VSS, G7 VSS, G8 VSS, G9 VSS, G10 VSS, G12 VSS, G13 VDD, H6 VSS, H7 VSS, H8 VSS, H9 VSS, H10 VSS, H12 VSS, H13 VDD33_USB, J6 VSS, J7 VSS, J8 VSS, J9 VSS, J10 VSS, J12 VDD, J13 VDD, K4 VDD, K6 VSS, K7 VSS, K8 VSS, K9 VSS, K10 VSS, L4 VSS, M1 VSSA, M8 VSS, M9 VSS, M10 VCAP, N1 VREF-, N8 VDD, N9 VDD, N10 VDD, P1 VREF+, R1 VDDA

## STM32L051K6U6
designator D?
Cortex-M0, 32MHz, 32KB ROM, 8KB RAM, 1.65...3.6V, UFQFN-32, -40...+85°C; Manufacturer: STMicroelectronics
footprint 32-QFN (5x5, pitch 0.5) (5x5 mm, pitch 0.5 mm, power pad)
pins: 0 PAD, 1 VDD, 2 PC14/OSC32_IN (io), 3 PC15/OSC32_OUT (io), 4 NRST (in), 5 VDDA, 6 PA0 (io), 7 PA1 (io), 8 PA2 (io), 9 PA3 (io), 10 PA4 (io), 11 PA5 (io), 12 PA6 (io), 13 PA7 (io), 14 PB0 (io), 15 PB1 (io), 16 PB2 (io), 17 VDD, 18 PA8 (io), 19 PA9 (io), 20 PA10 (io), 21 PA11 (io), 22 PA12 (io), 23 PA13/SWDIO (io), 24 PA14/SWCLK (io), 25 PA15 (io), 26 PB3 (io), 27 PB4 (io), 28 PB5 (io), 29 PB6 (io), 30 PB7 (io), 31 BOOT0 (in), 32 PB8 (io)

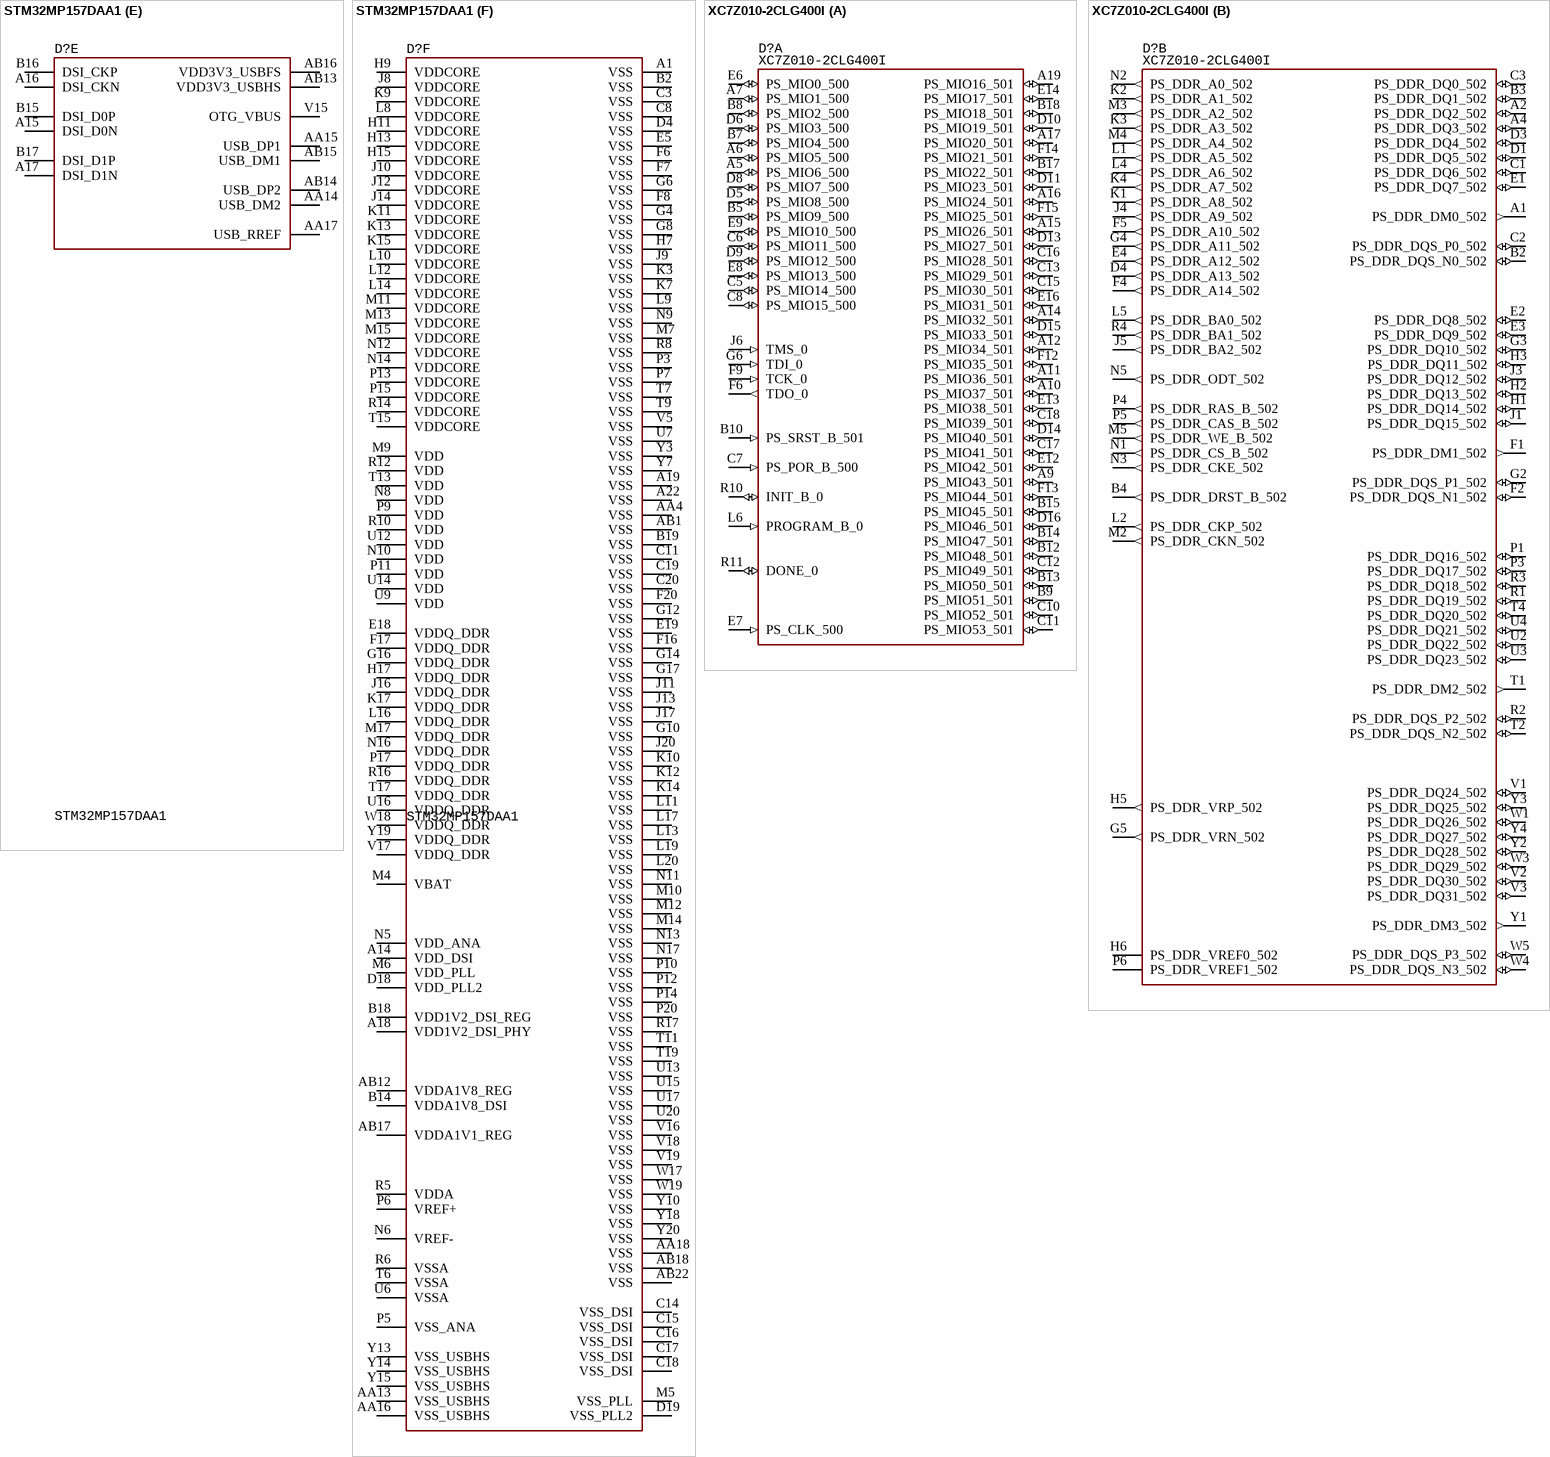
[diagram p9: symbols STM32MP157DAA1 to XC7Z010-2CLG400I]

## STM32MP157DAA1
designator D?  PartNumber: STM32MP157DAA1
Cortex-A7/M4, 800 MHz, 3D GPU, TFT, 448-LFBGA; Manufacturer: STMicroelectronics; ValueManufacturerPartNumber: IC ARM SoC, 2 core, 32-Bit, Cortex-A7/M4, 800MHz, DDR3, 3.3V, -40...+85°C, 448-LFBGA; Supply: 3.3V; Speed: 800MHz; CoreSize: 2 core, 32-Bit; TypeMemory: DDR3
footprint 448-LFBGA (18x18, pitch 0.8)
part A pins: A4 PE13 (io), A8 PD10 (io), A9 PD5 (io), A10 PE3 (io), A11 PA9 (io), A12 PB3 (io), A13 PB14 (io), AA3 PA0 (io), AA5 PB1 (io), AA6 PC5 (io), AA7 PB12 (io), AA8 PB5 (io), AA10 PF7 (io), AA11 PF6 (io), AB2 PA2 (io), AB3 PC1 (io), AB5 PB0 (io), AB6 PC4 (io), AB8 PB8 (io), AB9 PD11 (io), AB10 PF8 (io), AB11 PF9 (io), B4 PE14 (io), B9 PF1 (io), B10 PD1 (io), B11 PD3 (io), B12 PB15 (io), B13 PA8 (io), C4 PE15 (io), C5 PE0 (io), C9 PD4 (io), C10 PD0 (io), C12 PE5 (io), C13 PB4 (io), D5 PE11 (io), D7 PE1 (io), D9 PF5 (io), D12 PD2 (io), D13 PC7 (io), D14 PC9 (io), D15 PC11 (io), E4 PE12 (io), E9 PE6 (io), E10 PF0 (io), E11 PA15 (io), E12 PC12 (io), E13 PC6 (io), E14 PC8 (io), F9 PF4 (io), F10 PD7 (io), F11 PB7 (io), F12 PB9 (io), F13 PF2 (io), F14 PC10 (io), F15 PE4 (io), L1 PD15 (io), L3 PD6 (io), M1 PD8 (io), M2 PD9 (io), M3 PD14 (io), N2 PC13 (io), R3 PA14 (io), T4 PA3 (io), U3 PC3 (io), U5 PA5 (io), U10 PC0 (io), V3 PF3 (io), V4 PA1 (io), V6 PA4 (io), V7 PF14 (io), V8 PF12 (io), V9 PB10 (io), V10 PB13 (io), V12 PF10 (io), V13 PB2 (io), V14 PD13 (io), W3 PA13 (io), W6 PF15 (io), W7 PF13 (io), W8 PF11 (io), W9 PA6 (io), W10 PE7 (io), W11 PE9 (io), W12 PD12 (io), W13 PB6 (io), W14 PE10 (io), W16 PA12 (io), Y1 PC2 (io), Y2 PE2 (io), Y5 PB11 (io), Y9 PA7 (io), Y12 PE8 (io), Y16 PA11 (io), Y17 PA10 (io)
part B pins: A2 PH5 (io), A3 PH4 (io), A5 PK6 (io), A6 PK4 (io), A7 PJ13 (io), AA1 PG13 (io), AA2 PG14 (io), AA9 PG10 (io), AB4 PG4 (io), AB7 PH2 (io), B1 PH10 (io), B3 PH11 (io), B5 PK7 (io), B6 PK3 (io), B7 PJ14 (io), B8 PJ12 (io), C1 PH15 (io), C2 PH14 (io), C6 PK5 (io), C7 PJ15 (io), D1 PI0 (io), D2 PI14 (io), D3 PH13 (io), D6 PH8 (io), D8 PK0 (io), D10 PG15 (io), D11 PG6 (io), E1 PI2 (io), E2 PI1 (io), E3 PI3 (io), E6 PH9 (io), E7 PK1 (io), E8 PK2 (io), F1 PI7 (io), F2 PI5 (io), F3 PI15 (io), F4 PZ3 (io), F5 PH12 (io), G1 PZ4 (io), G2 PZ0 (io), G3 PZ6 (io), G5 PI6 (io), H1 PI13 (io), H2 PI12 (io), H3 PZ7 (io), H4 PZ5 (io), H5 PZ1 (io), H6 PJ8 (io), J1 PJ3 (io), J2 PJ0 (io), J3 PJ10 (io), J4 PG12 (io), J5 PI9 (io), J6 PI4 (io), K1 PJ5 (io), K2 PJ4 (io), K4 PJ2 (io), K5 PZ2 (io), K6 PJ11 (io), L2 PJ9 (io), L4 PJ7 (io), L5 PJ6 (io), L6 PJ1 (io), N1 PI8 (io), R4 ANA0, T3 PI11 (io), T5 ANA1, U4 PG3 (io), U8 PG5 (io), U11 PG11 (io), V11 PH6 (io), W1 PI10 (io), W2 PH7 (io), W4 PG2 (io), W5 PG0 (io), W15 PG9 (io), Y4 PG1 (io), Y6 PH3 (io), Y8 PG8 (io), Y11 PG7 (io)
part C pins: AA12 BYPASS_REG1V8 (in), D16 JTDI (in), D17 JTCK-SWCLK (in), E15 NJTRST (in), E16 JTDO-TRACESWO (out), E17 JTMS-SWDIO (io), N3 BOOT0 (in), N4 BOOT1 (in), P1 PC14/OSC32-IN (io), P2 PC15/OSC32-OUT (io), P4 BOOT2 (in), R1 NRST_CORE (in), R2 NRST (io), T1 PH0/OSC-IN (io), T2 PH1/OSC-OUT (io), U1 PWR_LP (out), U2 PDR_ON_CORE (in), V1 PWR_ON (out), V2 PDR_ON (in)
part D pins: A20 DDR_DQ20 (io), A21 DDR_DQ23 (io), AA19 DDR_ATO (out), AA20 DDR_DQ29 (io), AA21 DDR_DQ28 (io), AA22 DDR_DQM3 (out), AB19 DDR_VREF, AB20 DDR_DQ27 (io), AB21 DDR_DQ26 (io), B20 DDR_DQ19 (io), B21 DDR_DQ16 (io), B22 DDR_DQS2N (io), C21 DDR_DQS2P (io), C22 DDR_DQM2 (out), D20 DDR_DQ22 (io), D21 DDR_DQ17 (io), D22 DDR_DQ18 (io), E20 DDR_DQ3 (io), E21 DDR_DQ0 (io), E22 DDR_DQ21 (io), F18 DDR_A7 (out), F19 DDR_RESETN (out), F21 DDR_DQ1 (io), G18 DDR_A13 (out), G19 DDR_DQ7 (io), G20 DDR_DQM0 (out), G21 DDR_DQS0N (io), G22 DDR_DQS0P (io), H18 DDR_A9 (out), H19 DDR_A5 (out), H20 DDR_DQ5 (io), H21 DDR_DQ2 (io), H22 DDR_DQ6 (io), J18 DDR_A2 (out), J19 DDR_A3 (out), J21 DDR_DQ4 (io), K18 DDR_BA2 (out), K19 DDR_A0 (out), K20 DDR_BA0 (out), K21 DDR_DTO1 (out), K22 DDR_ZQ, L18 DDR_CSN (out), L21 DDR_ODT (out), L22 DDR_DTO0 (out), M18 DDR_A1 (out), M19 DDR_A15 (out), M20 DDR_RASN (out), M21 DDR_WEN (out), M22 DDR_CASN (out), N18 DDR_A10 (out), N19 DDR_A12 (out), N20 DDR_CLKP (out), N21 DDR_CLKN (out), N22 DDR_DQ8 (io), P18 DDR_A14 (out), P19 DDR_A11 (out), P21 DDR_DQ10 (io), R18 DDR_BA1 (in), R19 DDR_CKE (in), R20 DDR_DQ13 (io), R21 DDR_DQ9 (io), R22 DDR_DQS1N (io), T18 DDR_A4 (out), T20 DDR_DQ11 (io), T21 DDR_DQM1 (out), T22 DDR_DQS1P (io), U18 DDR_A8 (out), U19 DDR_A6 (out), U21 DDR_DQ14 (io), V20 DDR_DQ12 (io), V21 DDR_DQ15 (io), V22 DDR_DQ24 (io), W20 DDR_DQ25 (io), W21 DDR_DQ31 (io), W22 DDR_DQ30 (io), Y21 DDR_DQS3P (io), Y22 DDR_DQS3N (io)
part E pins: A15 DSI_D0N, A16 DSI_CKN, A17 DSI_D1N, AA14 USB_DM2, AA15 USB_DP1, AA17 USB_RREF, AB13 VDD3V3_USBHS (power), AB14 USB_DP2, AB15 USB_DM1, AB16 VDD3V3_USBFS (power), B15 DSI_D0P, B16 DSI_CKP, B17 DSI_D1P, V15 OTG_VBUS
part F pins: A1 VSS (power), A14 VDD_DSI (power), A18 VDD1V2_DSI_PHY (power), A19 VSS (power), A22 VSS (power), AA4 VSS (power), AA13 VSS_USBHS (power), AA16 VSS_USBHS (power), AA18 VSS (power), AB1 VSS (power), AB12 VDDA1V8_REG (power), AB17 VDDA1V1_REG (power), AB18 VSS (power), AB22 VSS (power), B2 VSS (power), B14 VDDA1V8_DSI (power), B18 VDD1V2_DSI_REG (power), B19 VSS (power), C3 VSS (power), C8 VSS (power), C11 VSS (power), C14 VSS_DSI (power), C15 VSS_DSI (power), C16 VSS_DSI (power), C17 VSS_DSI (power), C18 VSS_DSI (power), C19 VSS (power), C20 VSS (power), D4 VSS (power), D18 VDD_PLL2 (power), D19 VSS_PLL2 (power), E5 VSS (power), E18 VDDQ_DDR (power), E19 VSS (power), F6 VSS (power), F7 VSS (power), F8 VSS (power), F16 VSS (power), F17 VDDQ_DDR (power), F20 VSS (power), G4 VSS (power), G6 VSS (power), G8 VSS (power), G10 VSS (power), G12 VSS (power), G14 VSS (power), G16 VDDQ_DDR (power), G17 VSS (power), H7 VSS (power), H9 VDDCORE (power), H11 VDDCORE (power), H13 VDDCORE (power), H15 VDDCORE (power), H17 VDDQ_DDR (power), J8 VDDCORE (power), J9 VSS (power), J10 VDDCORE (power), J11 VSS (power), J12 VDDCORE (power), J13 VSS (power), J14 VDDCORE (power), J16 VDDQ_DDR (power), J17 VSS (power), J20 VSS (power), K3 VSS (power), K7 VSS (power), K9 VDDCORE (power), K10 VSS (power), K11 VDDCORE (power), K12 VSS (power), K13 VDDCORE (power), K14 VSS (power), K15 VDDCORE (power), K17 VDDQ_DDR (power), L8 VDDCORE (power), L9 VSS (power), L10 VDDCORE (power), L11 VSS (power), L12 VDDCORE (power), L13 VSS (power), L14 VDDCORE (power), L16 VDDQ_DDR (power), L17 VSS (power), L19 VSS (power), L20 VSS (power), M4 VBAT (power), M5 VSS_PLL (power), M6 VDD_PLL (power), M7 VSS (power), M9 VDD (power), M10 VSS (power), M11 VDDCORE (power), M12 VSS (power), M13 VDDCORE (power), M14 VSS (power), M15 VDDCORE (power), M17 VDDQ_DDR (power), N5 VDD_ANA (power), N6 VREF- (power), N8 VDD (power), N9 VSS (power), N10 VDD (power), N11 VSS (power), N12 VDDCORE (power), N13 VSS (power), N14 VDDCORE (power), N16 VDDQ_DDR (power), N17 VSS (power), P3 VSS (power), P5 VSS_ANA (power), P6 VREF+ (power), P7 VSS (power), P9 VDD (power), P10 VSS (power), P11 VDD (power), P12 VSS (power), P13 VDDCORE (power), P14 VSS (power), P15 VDDCORE (power), P17 VDDQ_DDR (power), P20 VSS (power), R5 VDDA (power), R6 VSSA (power), R8 VSS (power), R10 VDD (power), R12 VDD (power), R14 VDDCORE (power), R16 VDDQ_DDR (power), R17 VSS (power), T6 VSSA (power), T7 VSS (power), T9 VSS (power), T11 VSS (power), T13 VDD (power), T15 VDDCORE (power), T17 VDDQ_DDR (power), T19 VSS (power), U6 VSSA (power), U7 VSS (power), U9 VDD (power), U12 VDD (power), U13 VSS (power), U14 VDD (power), U15 VSS (power), U16 VDDQ_DDR (power), U17 VSS (power), U20 VSS (power), V5 VSS (power), V16 VSS (power), V17 VDDQ_DDR (power), V18 VSS (power), V19 VSS (power), W17 VSS (power), W18 VDDQ_DDR (power), W19 VSS (power), Y3 VSS (power), Y7 VSS (power), Y10 VSS (power), Y13 VSS_USBHS (power), Y14 VSS_USBHS (power), Y15 VSS_USBHS (power), Y18 VSS (power), Y19 VDDQ_DDR (power), Y20 VSS (power)

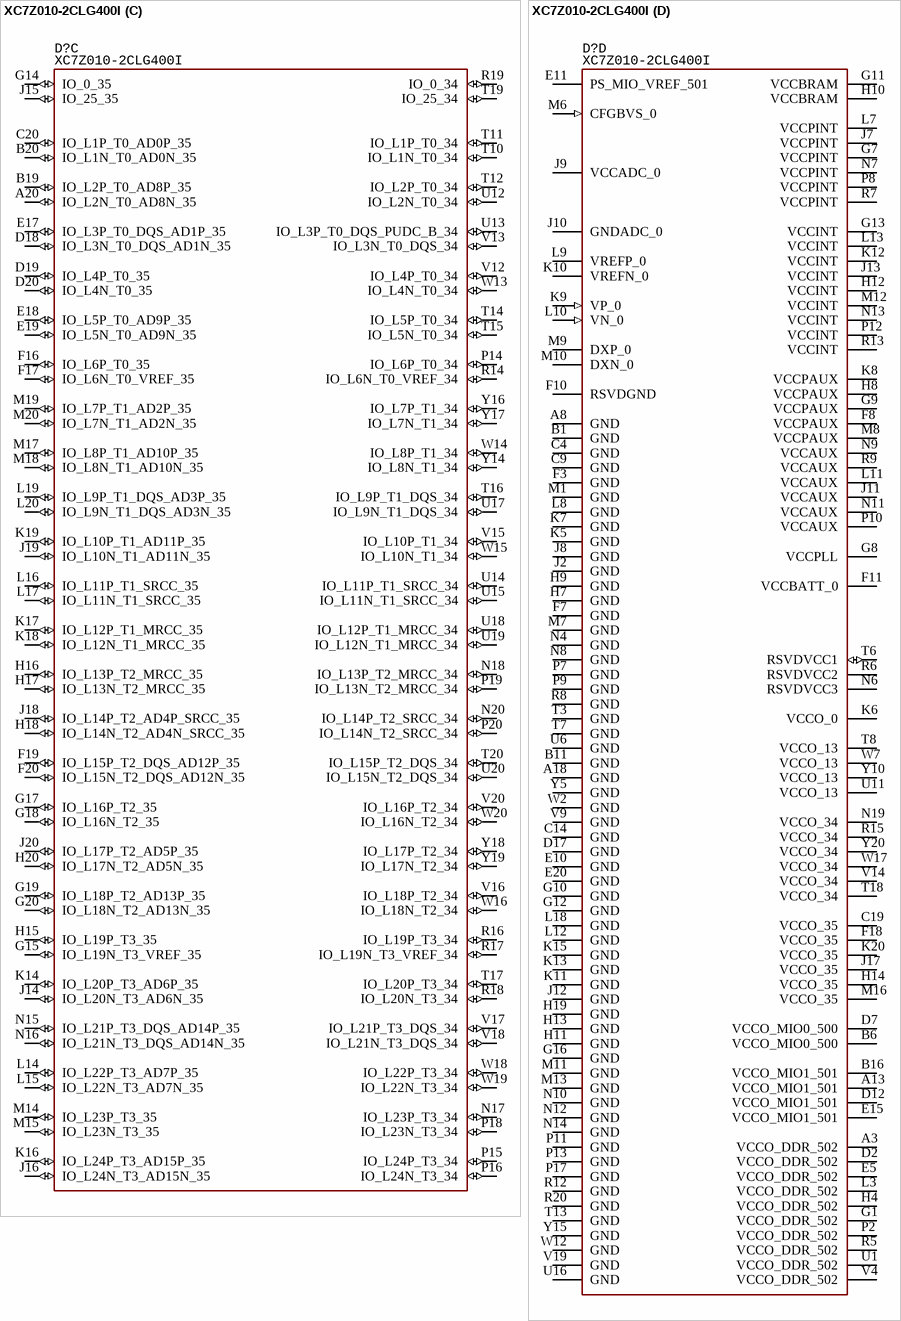
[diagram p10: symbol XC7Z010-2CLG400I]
